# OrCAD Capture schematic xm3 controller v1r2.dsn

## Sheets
1 Revision History: title: Controller; rev: V1.2; company: Wolfspeed; note: 535 W Research Center Blvd.; note: Fayetteville, AR, 72701
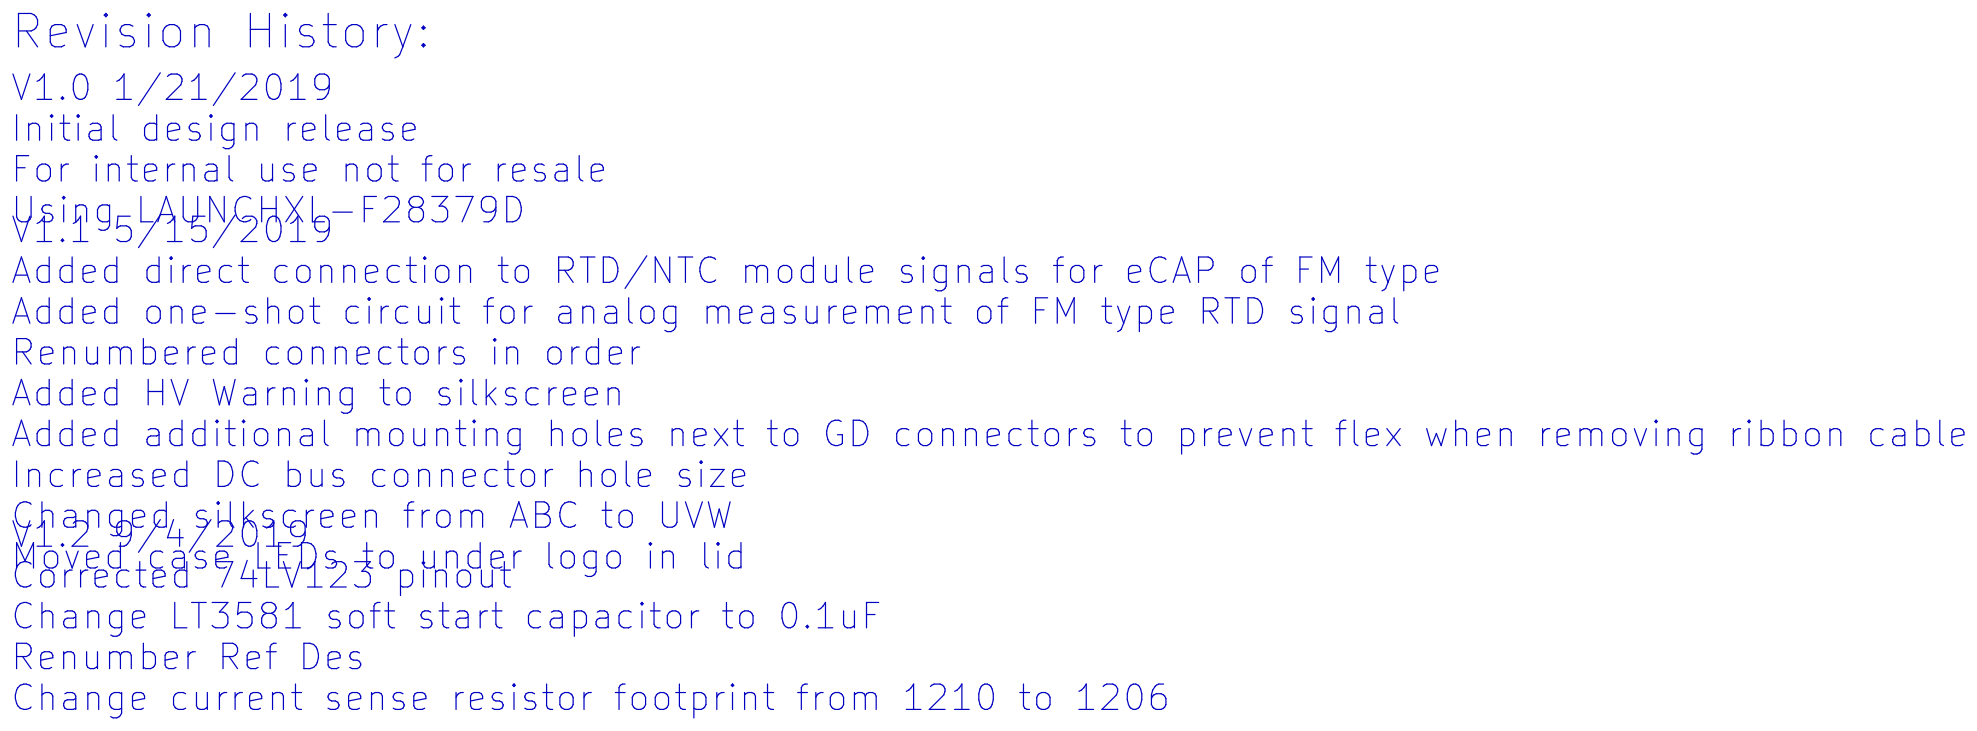
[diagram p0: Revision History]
2 Power Supply: size A
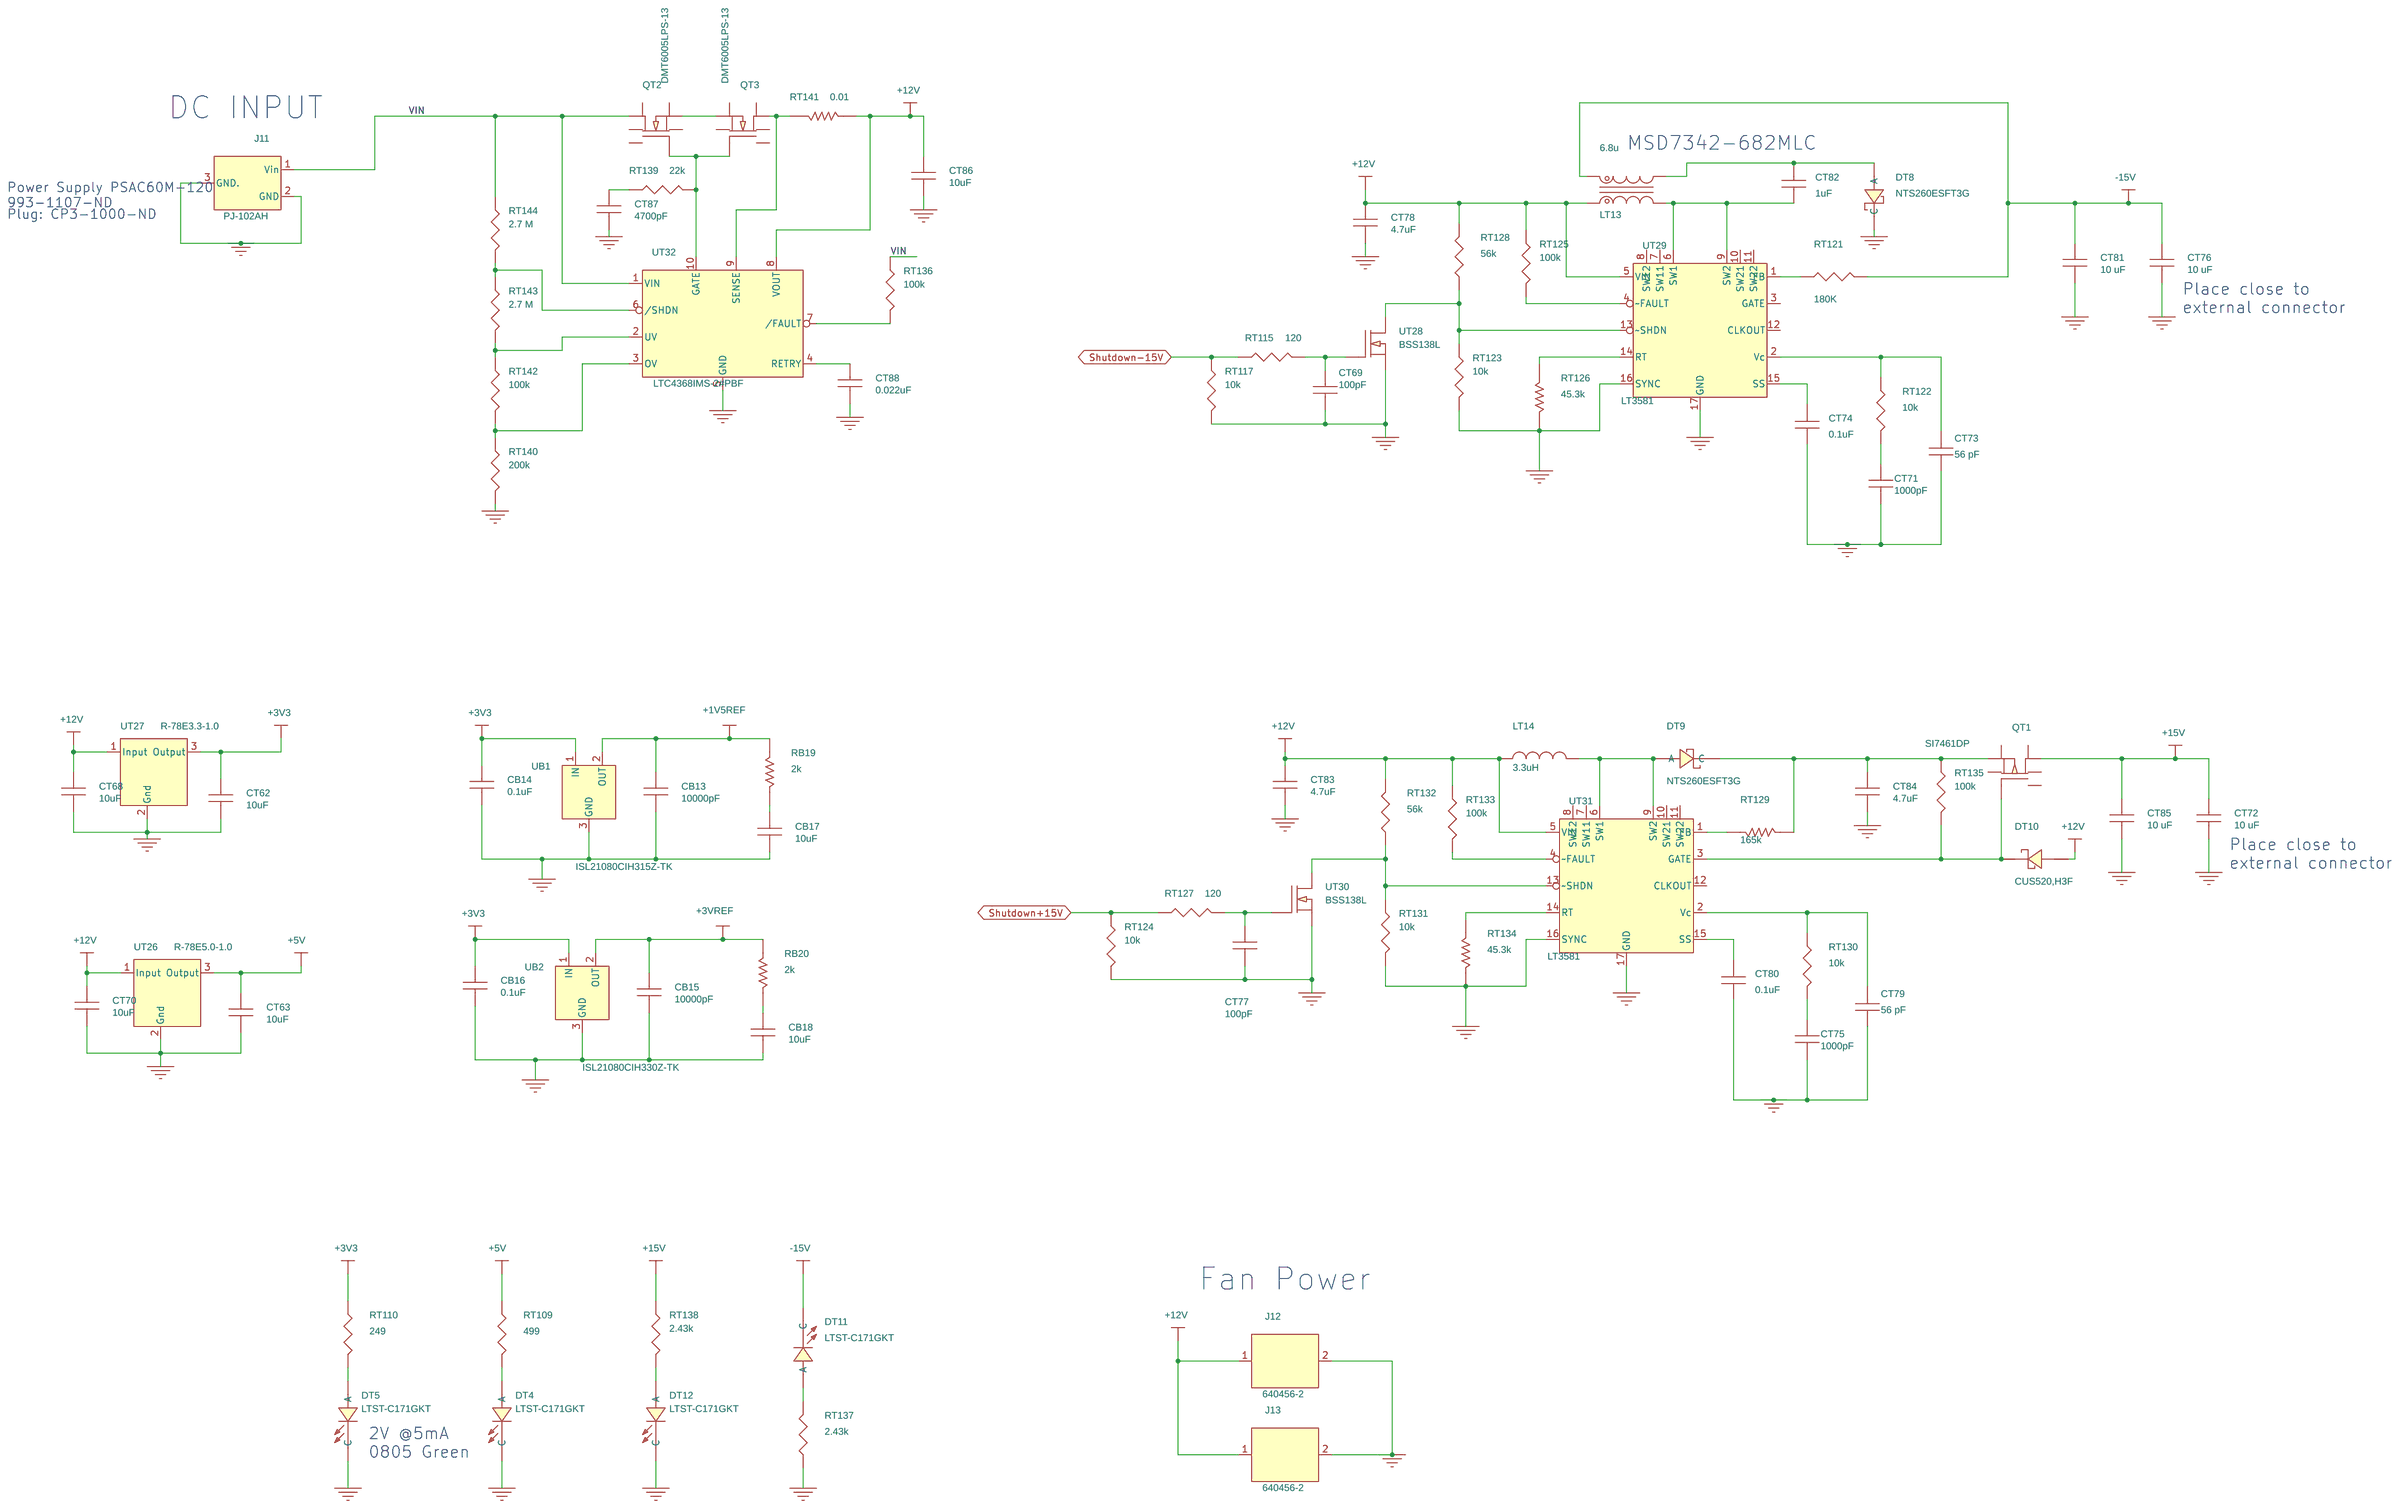
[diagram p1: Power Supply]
3 Voltage Sense: size A
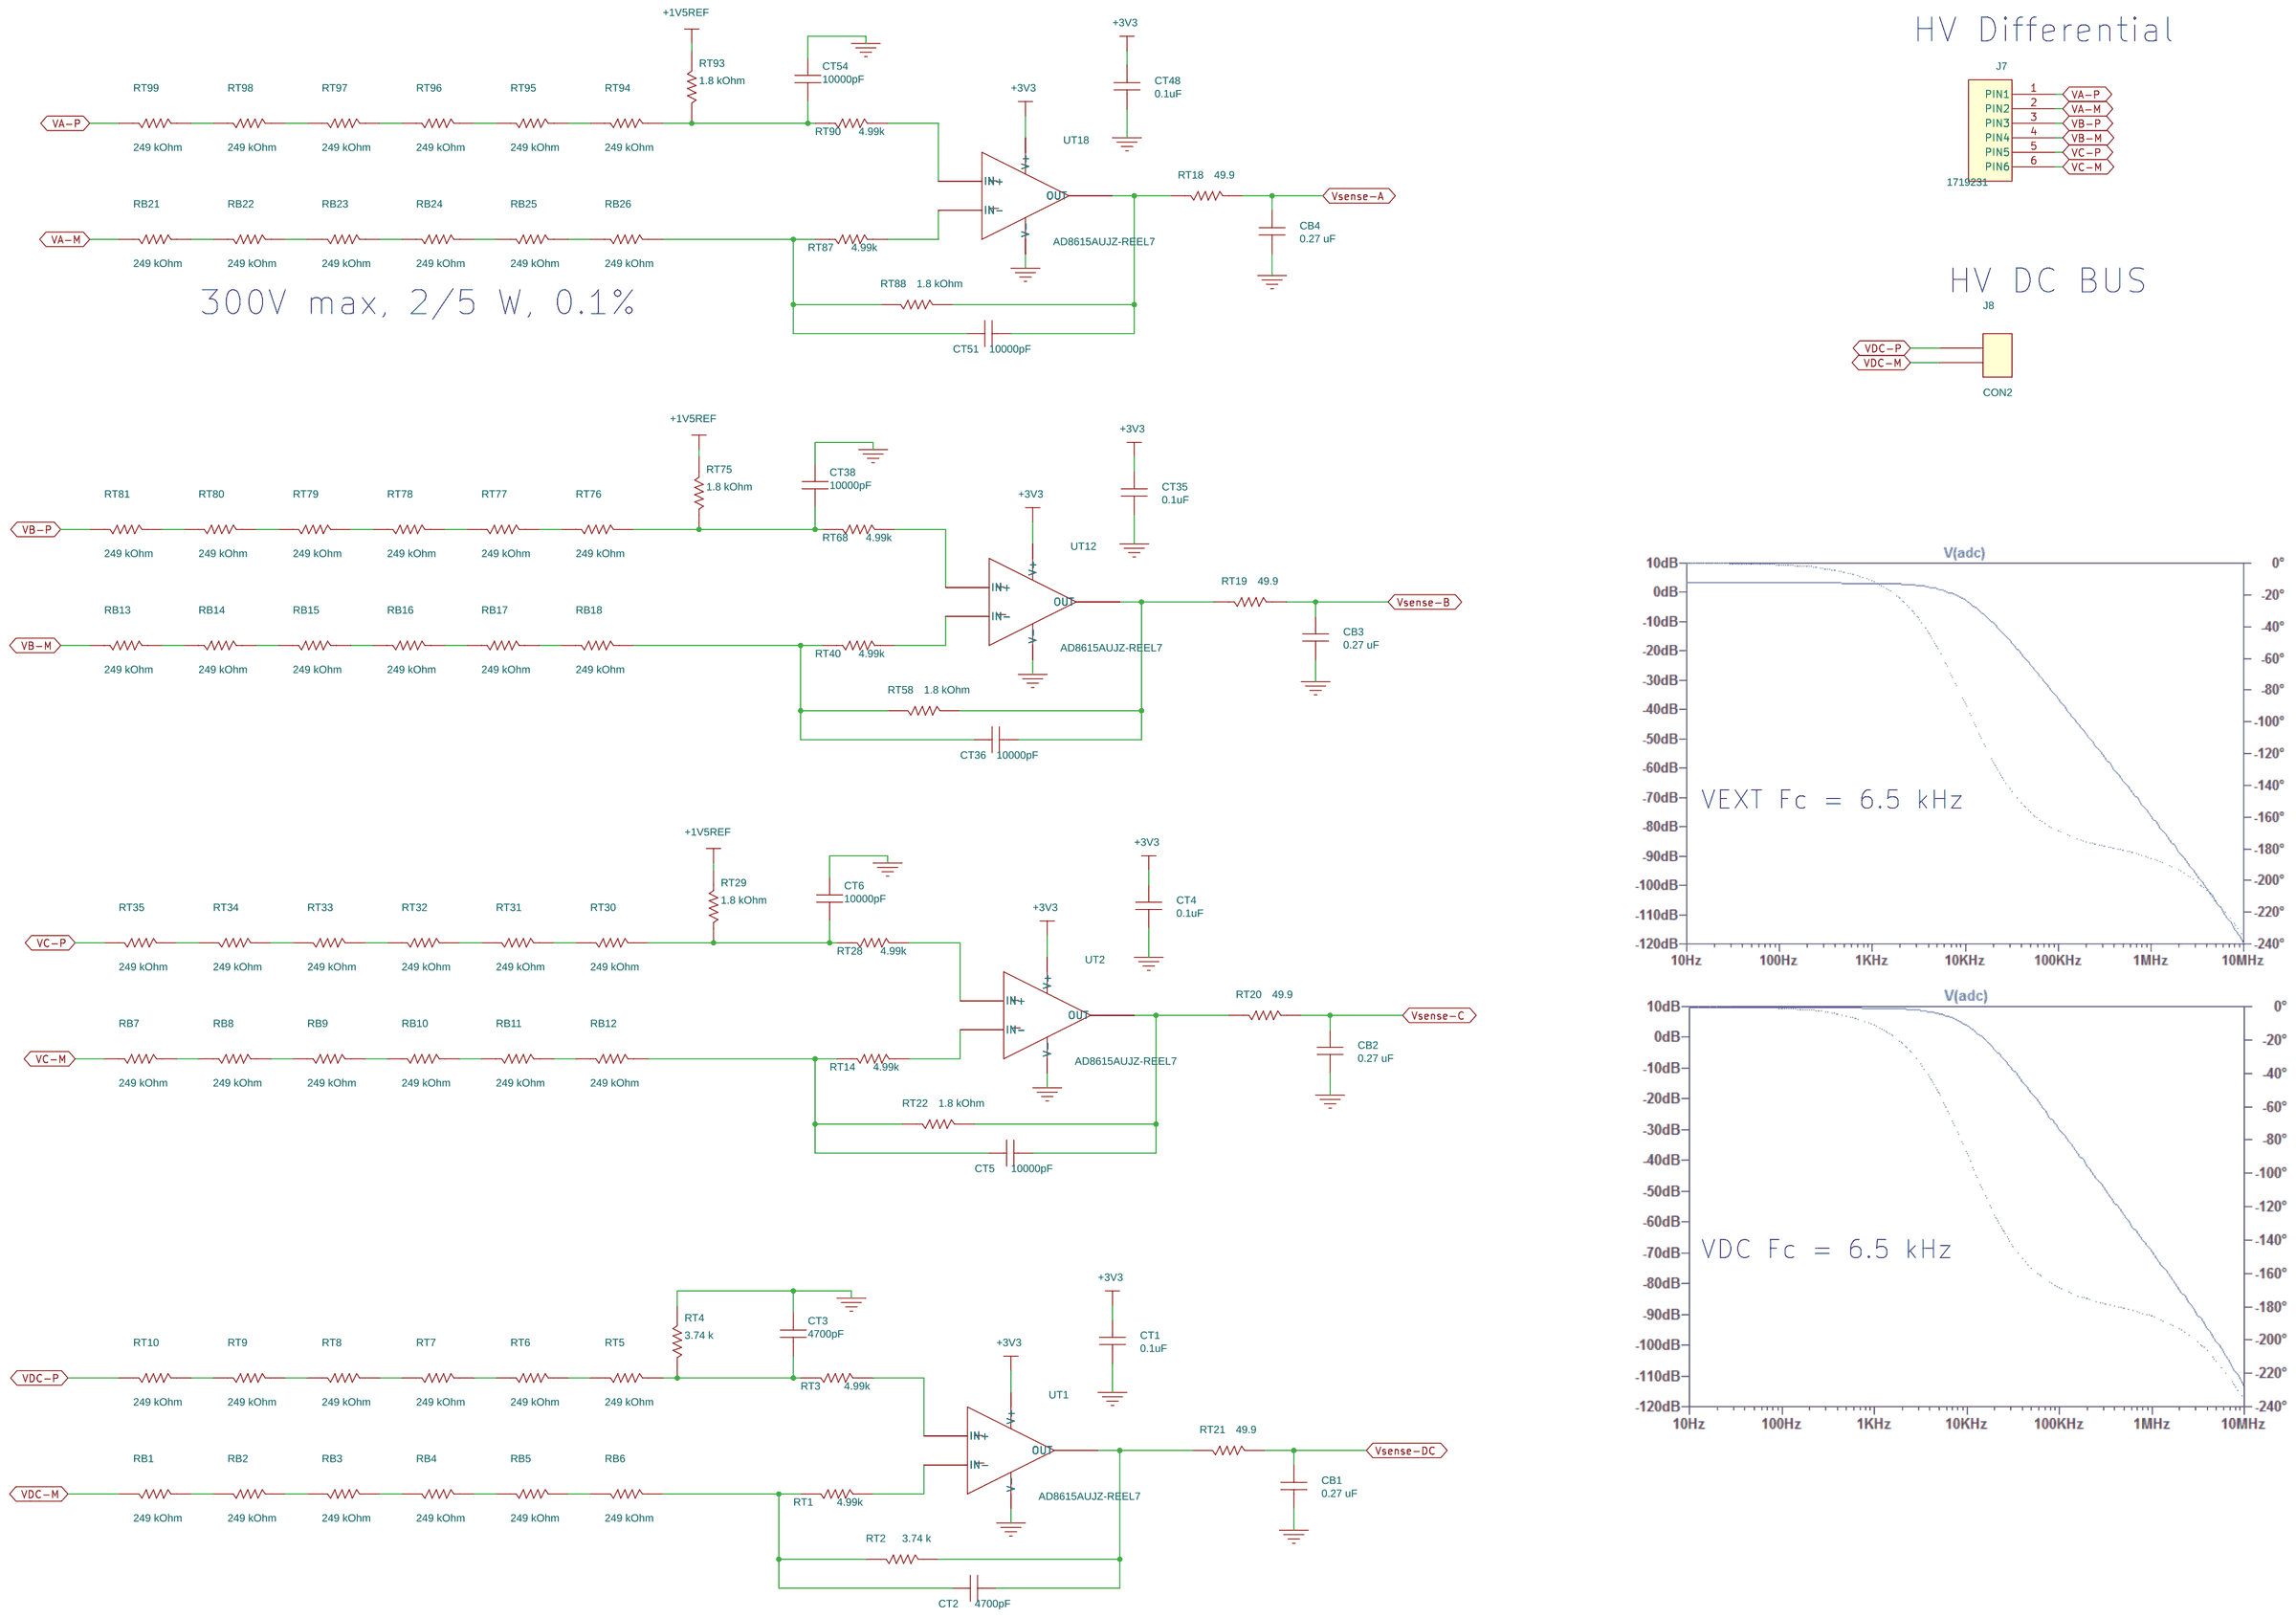
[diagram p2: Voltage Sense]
4 CAN: size A
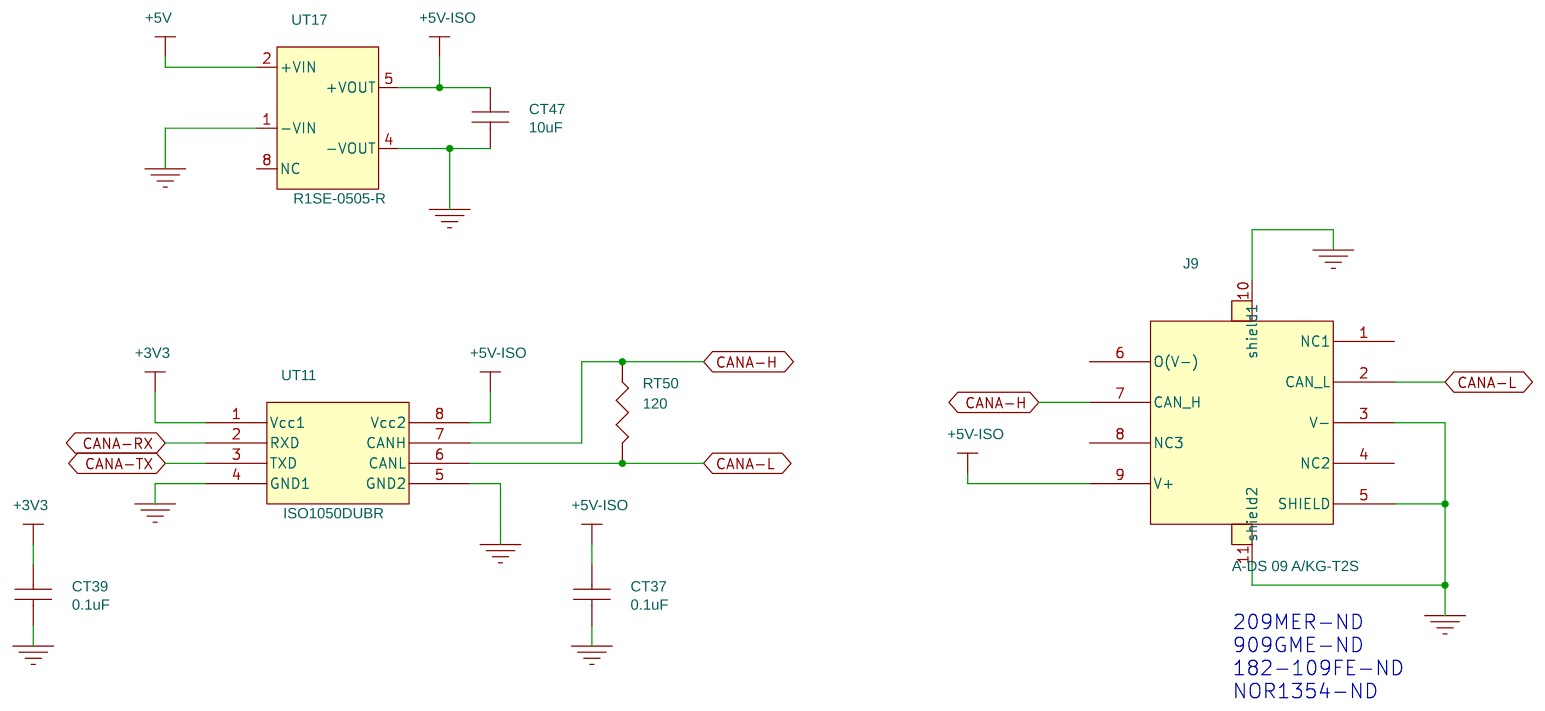
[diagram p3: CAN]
5 Temperature Sense: size A
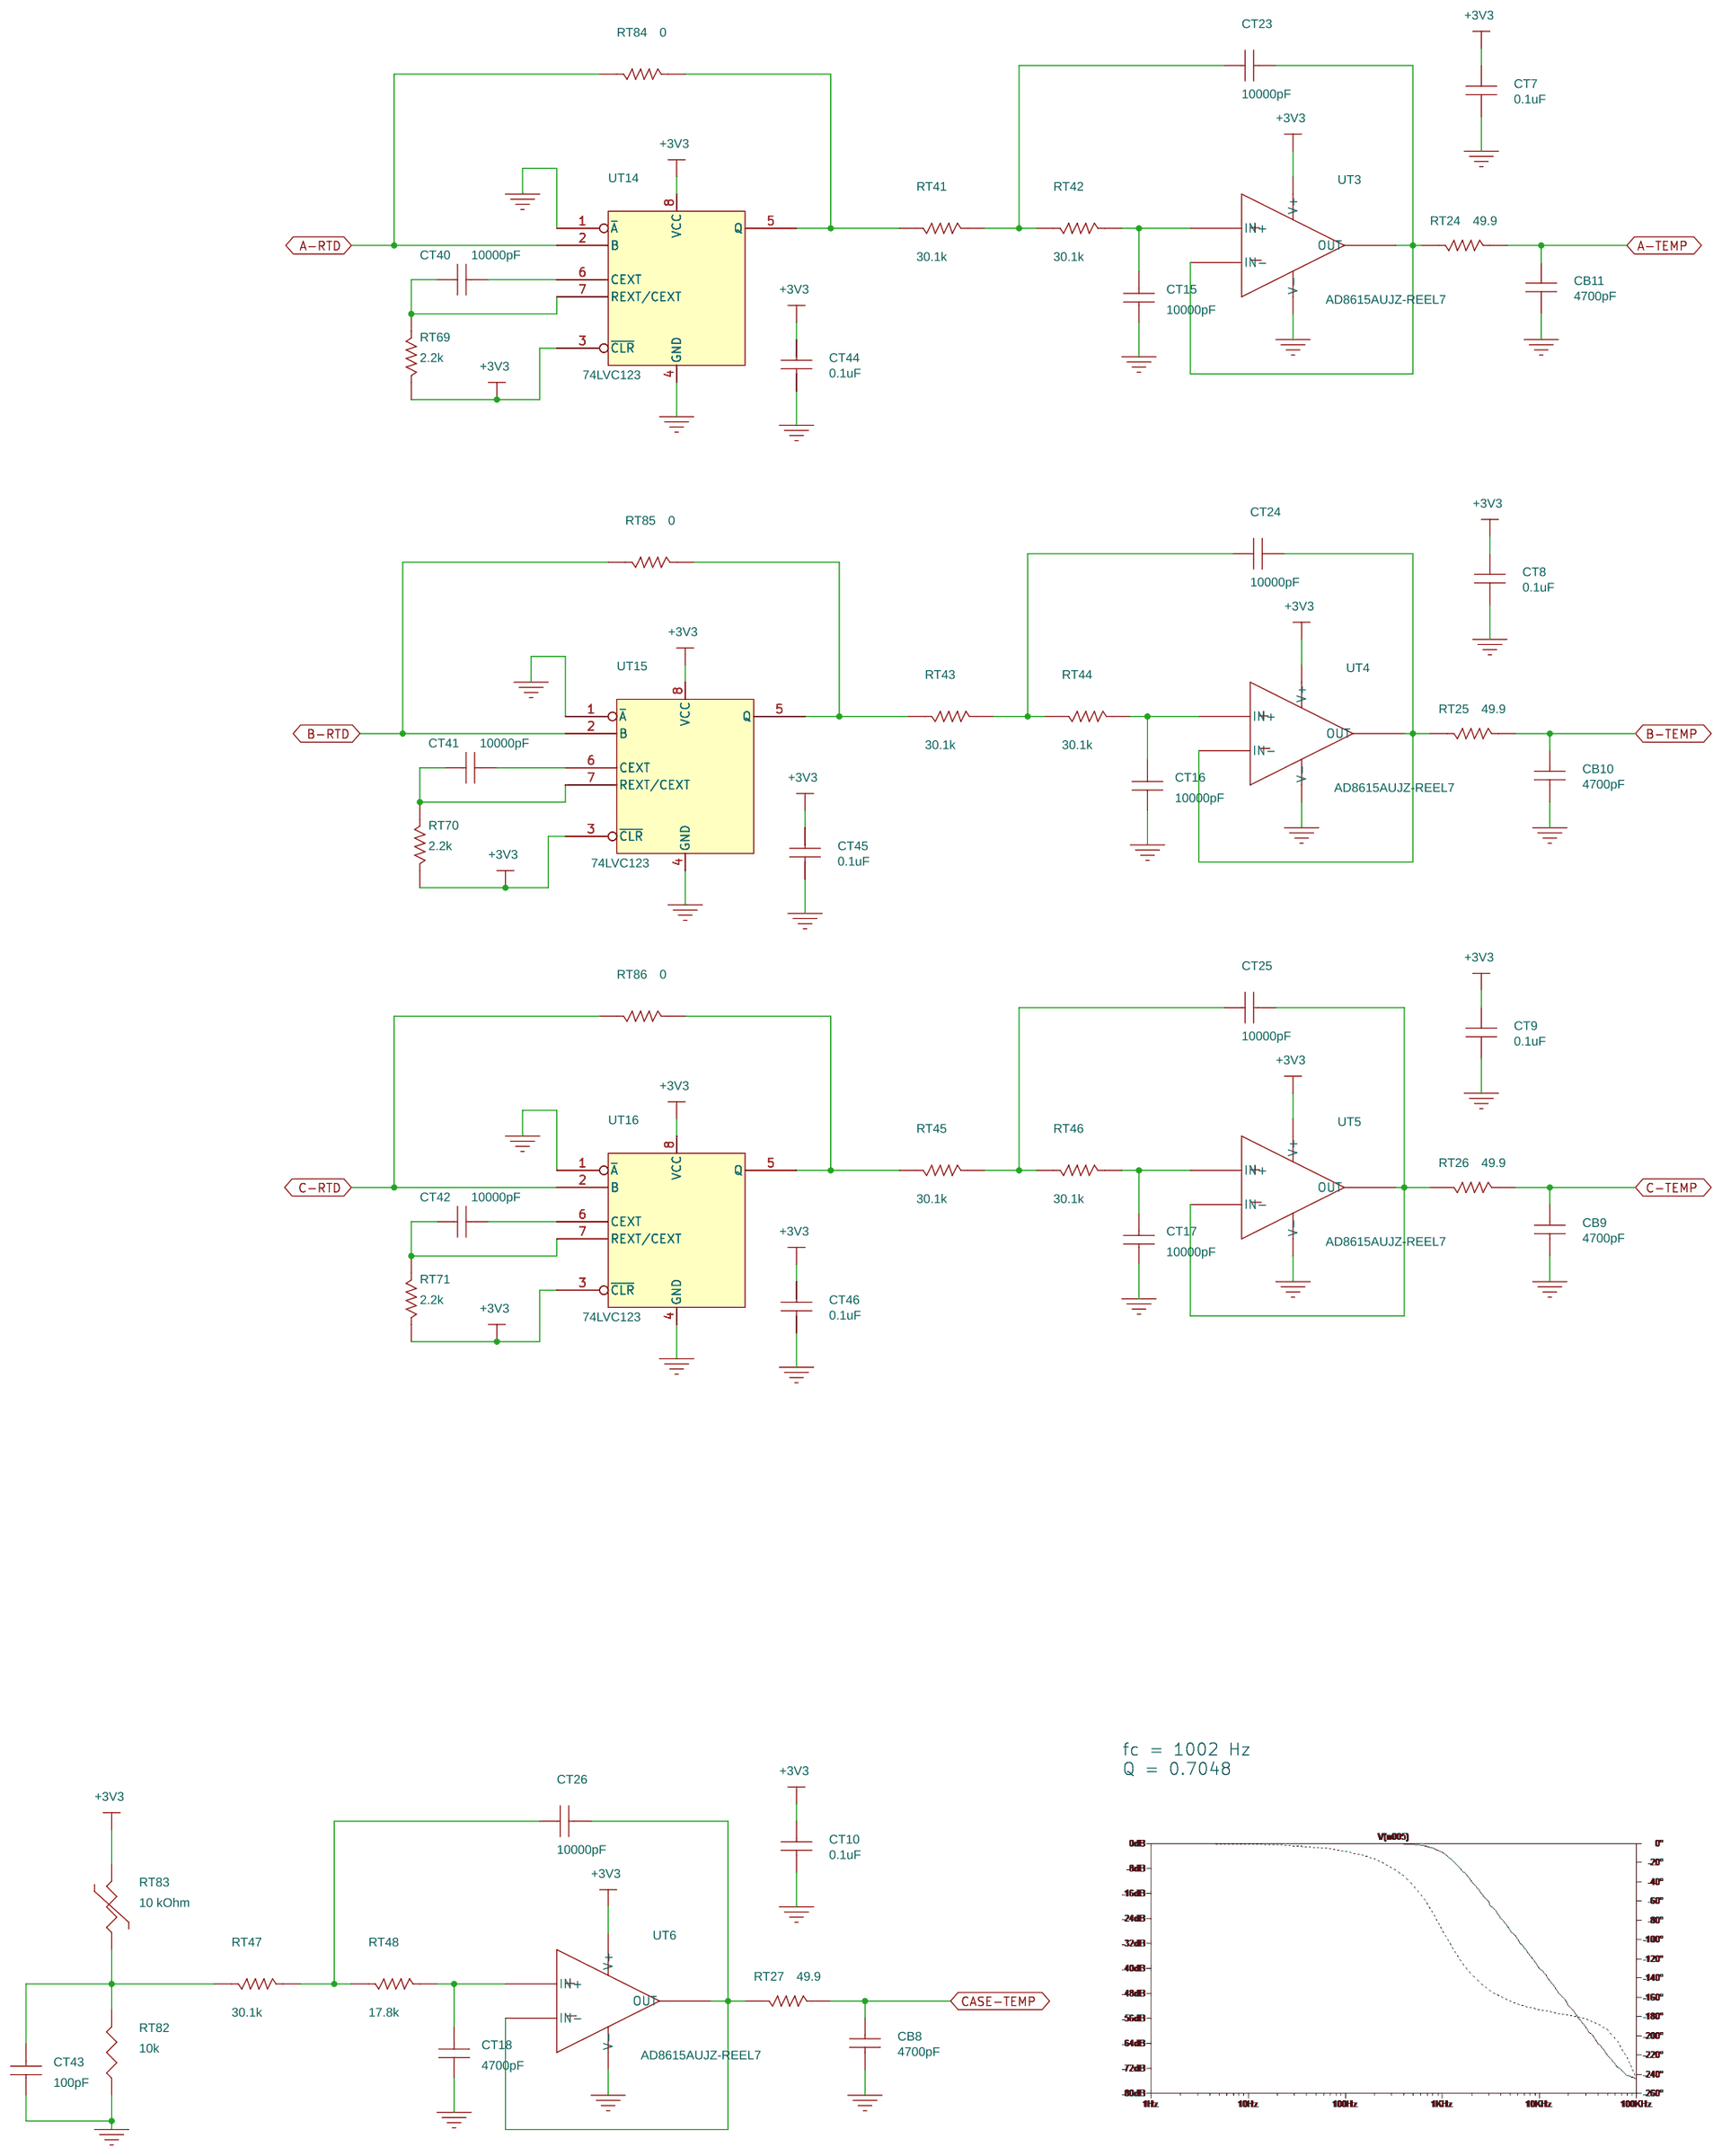
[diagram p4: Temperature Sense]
6 Current Sensors: size A
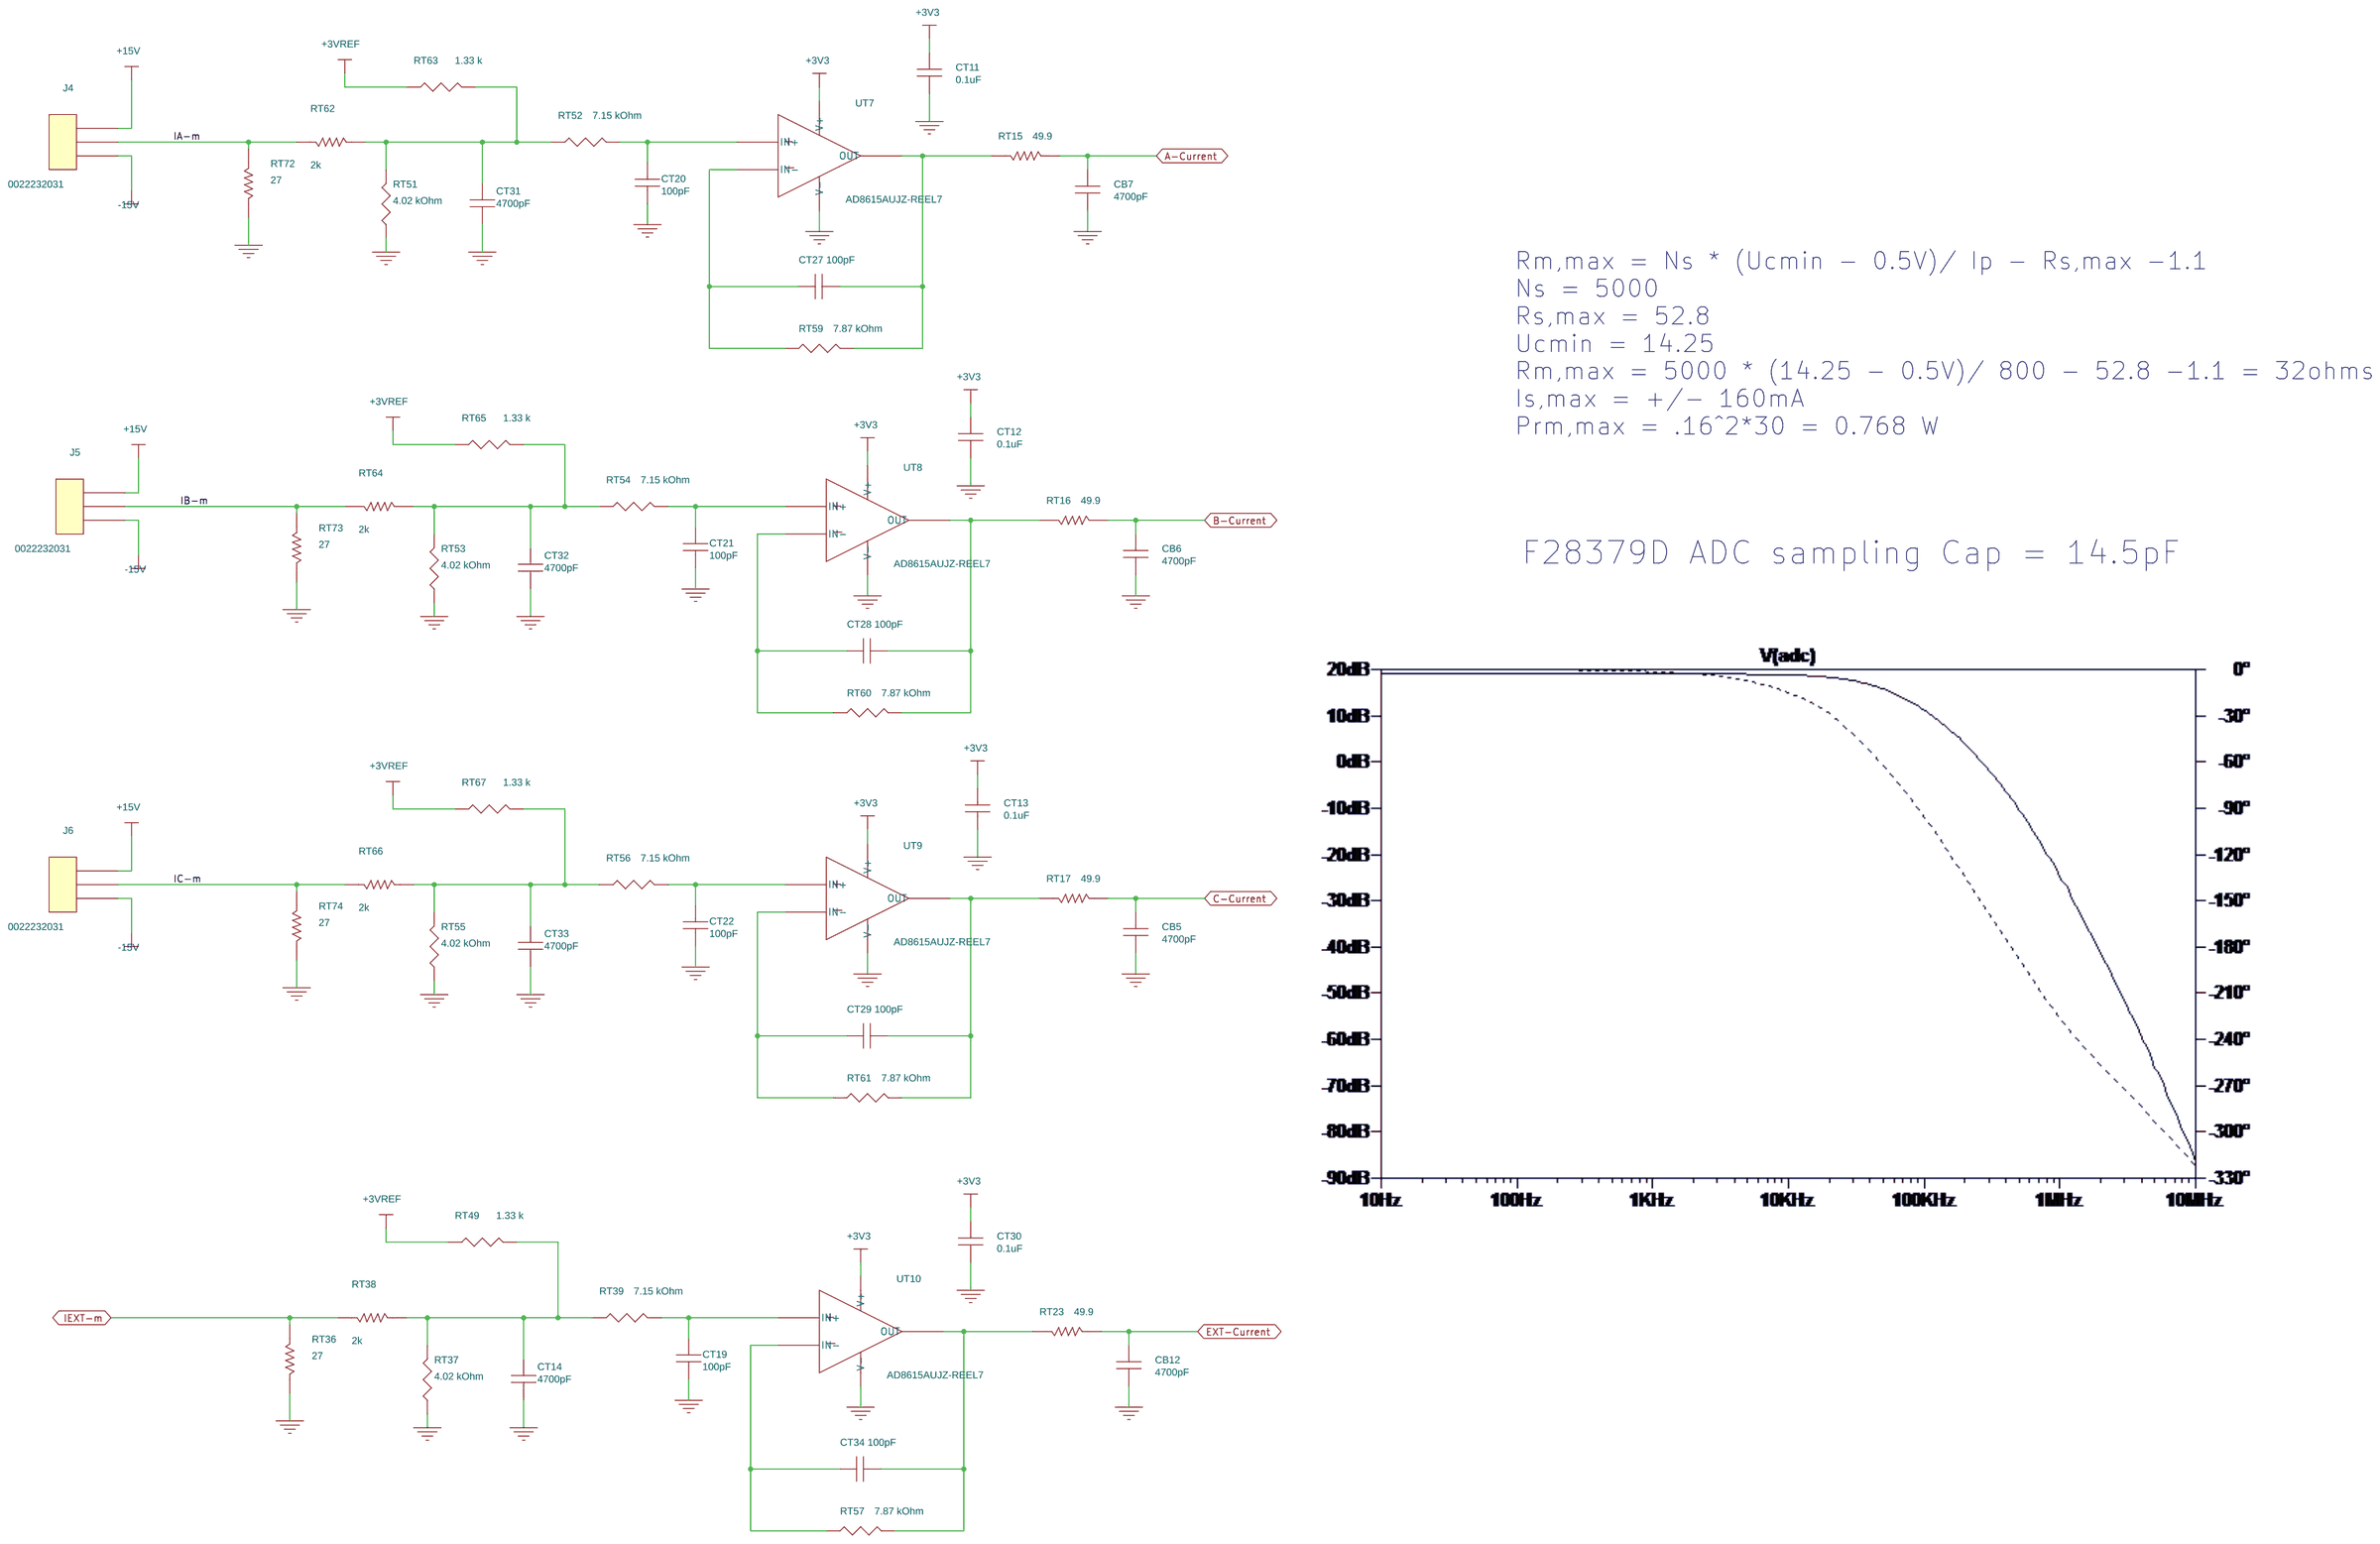
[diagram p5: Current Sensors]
7 LAUNCHPAD: size A
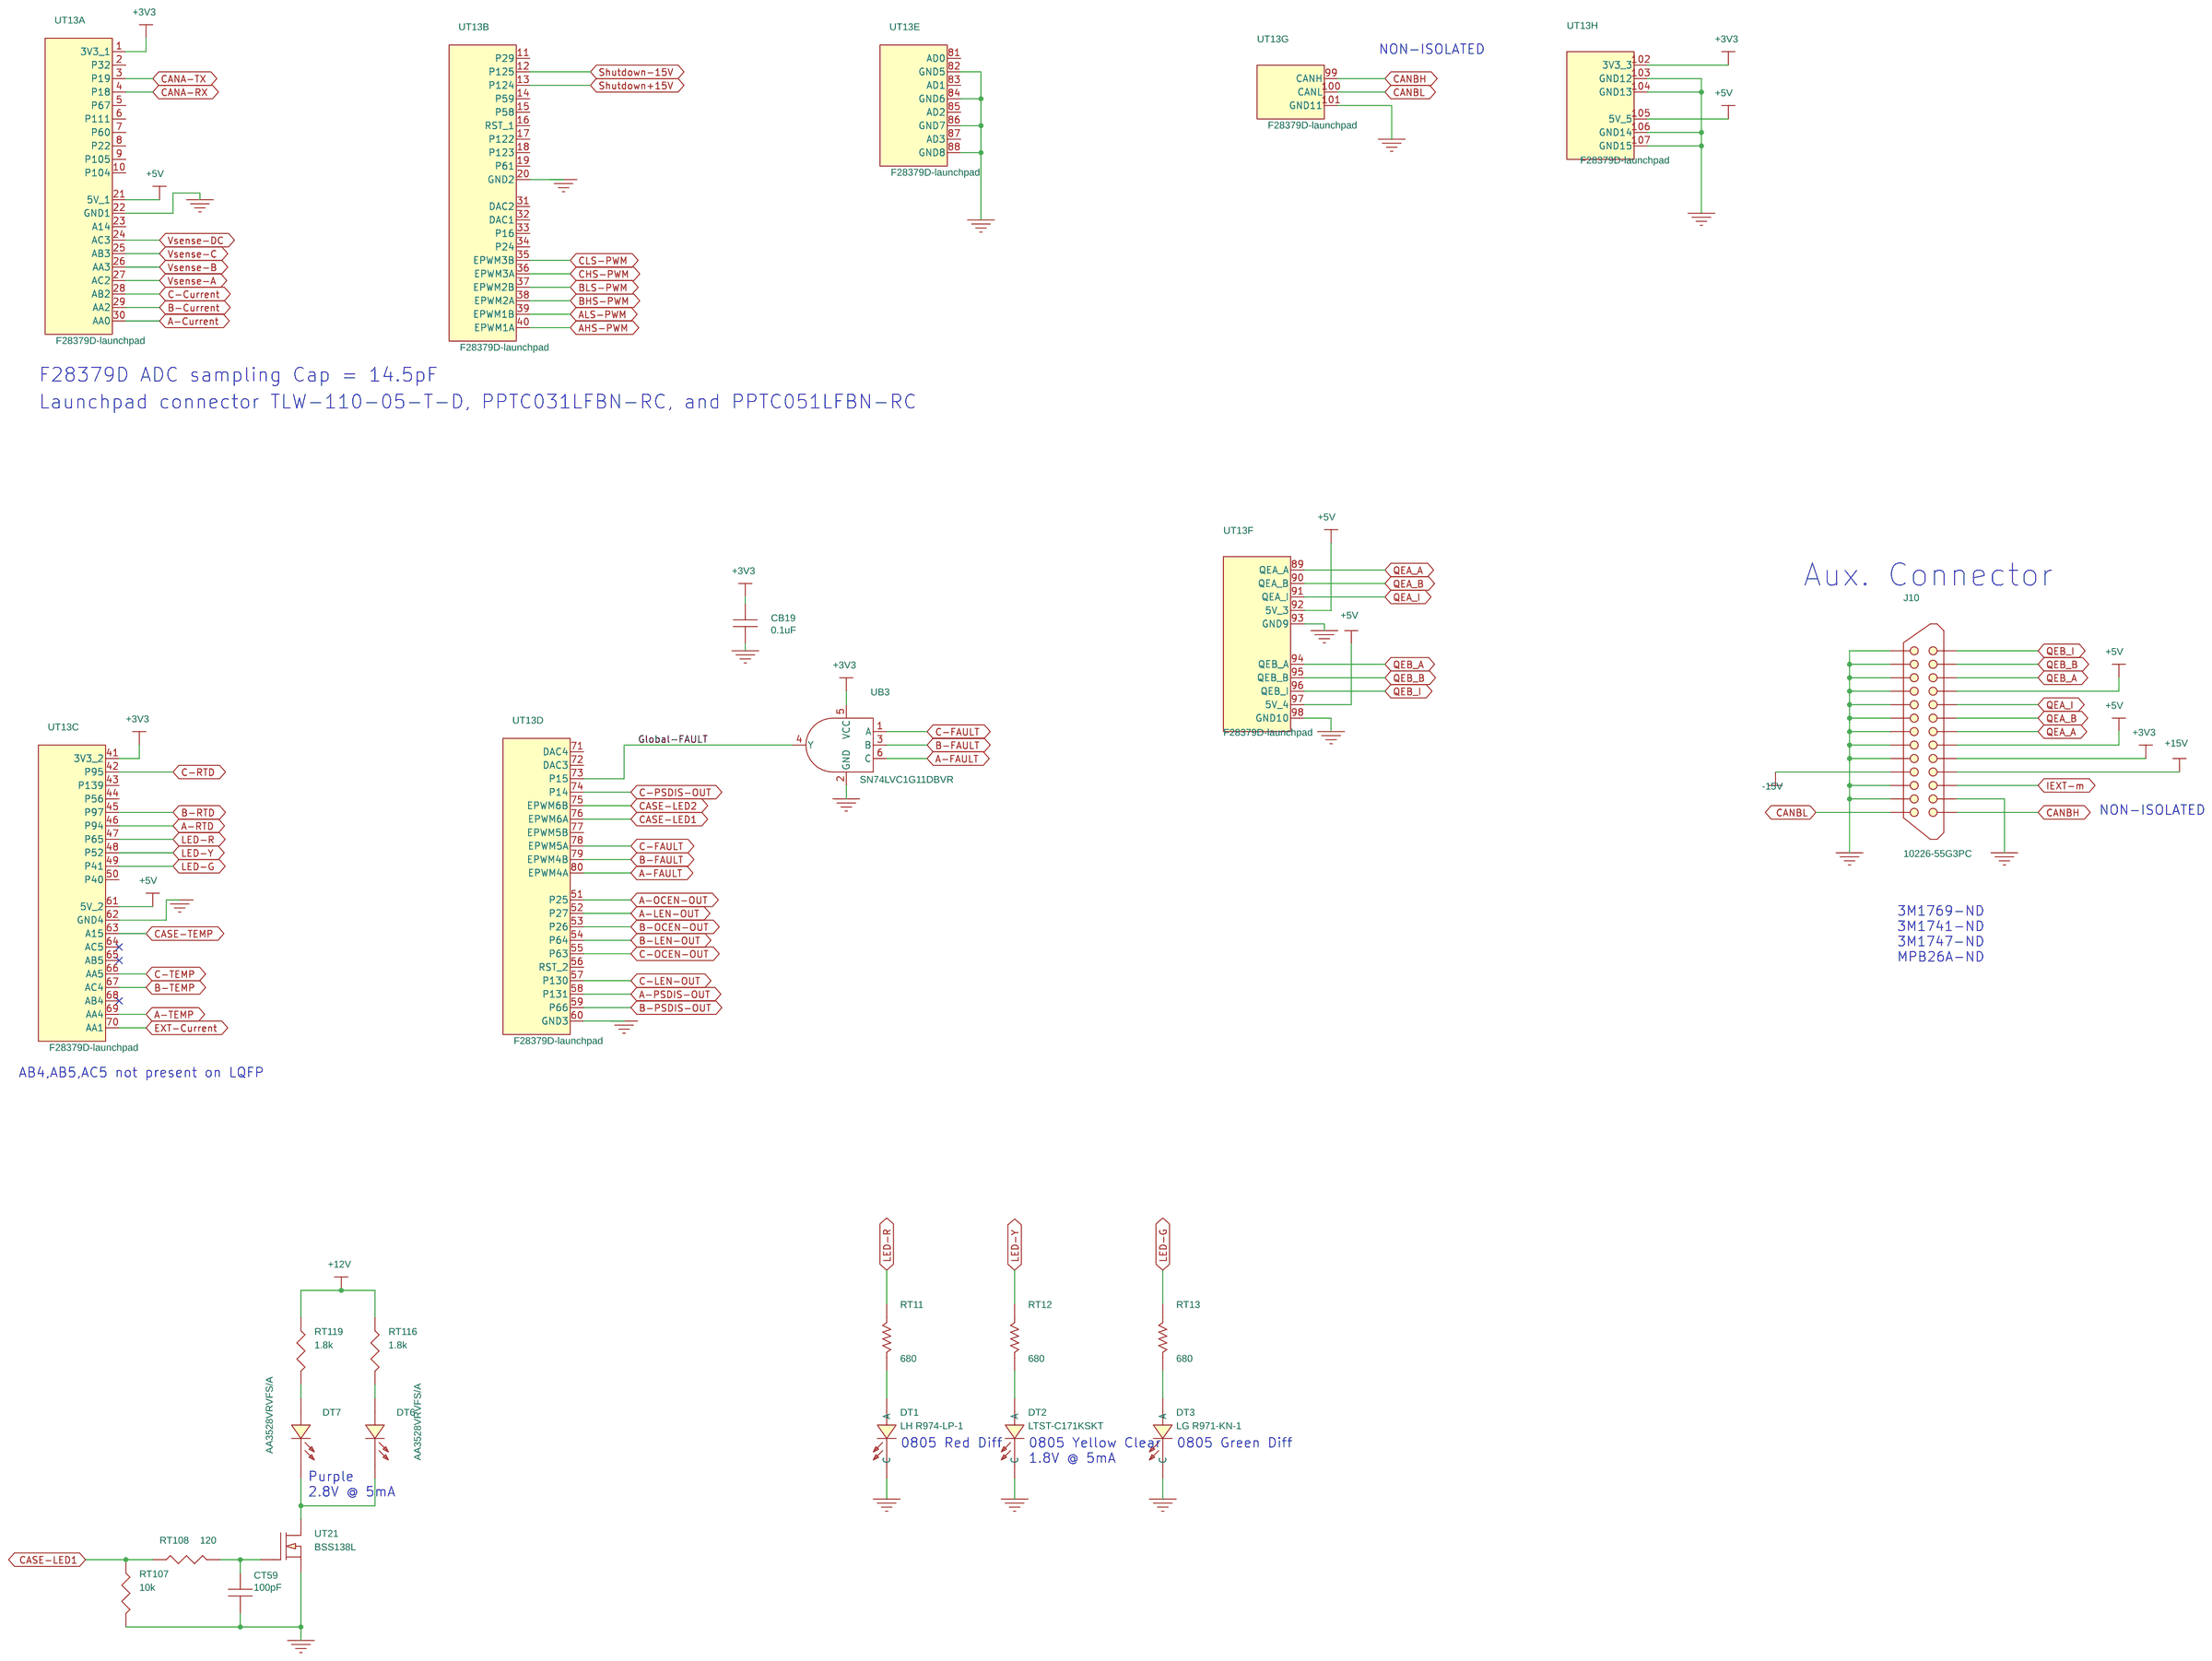
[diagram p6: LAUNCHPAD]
8 Gate Driver Interface: size A
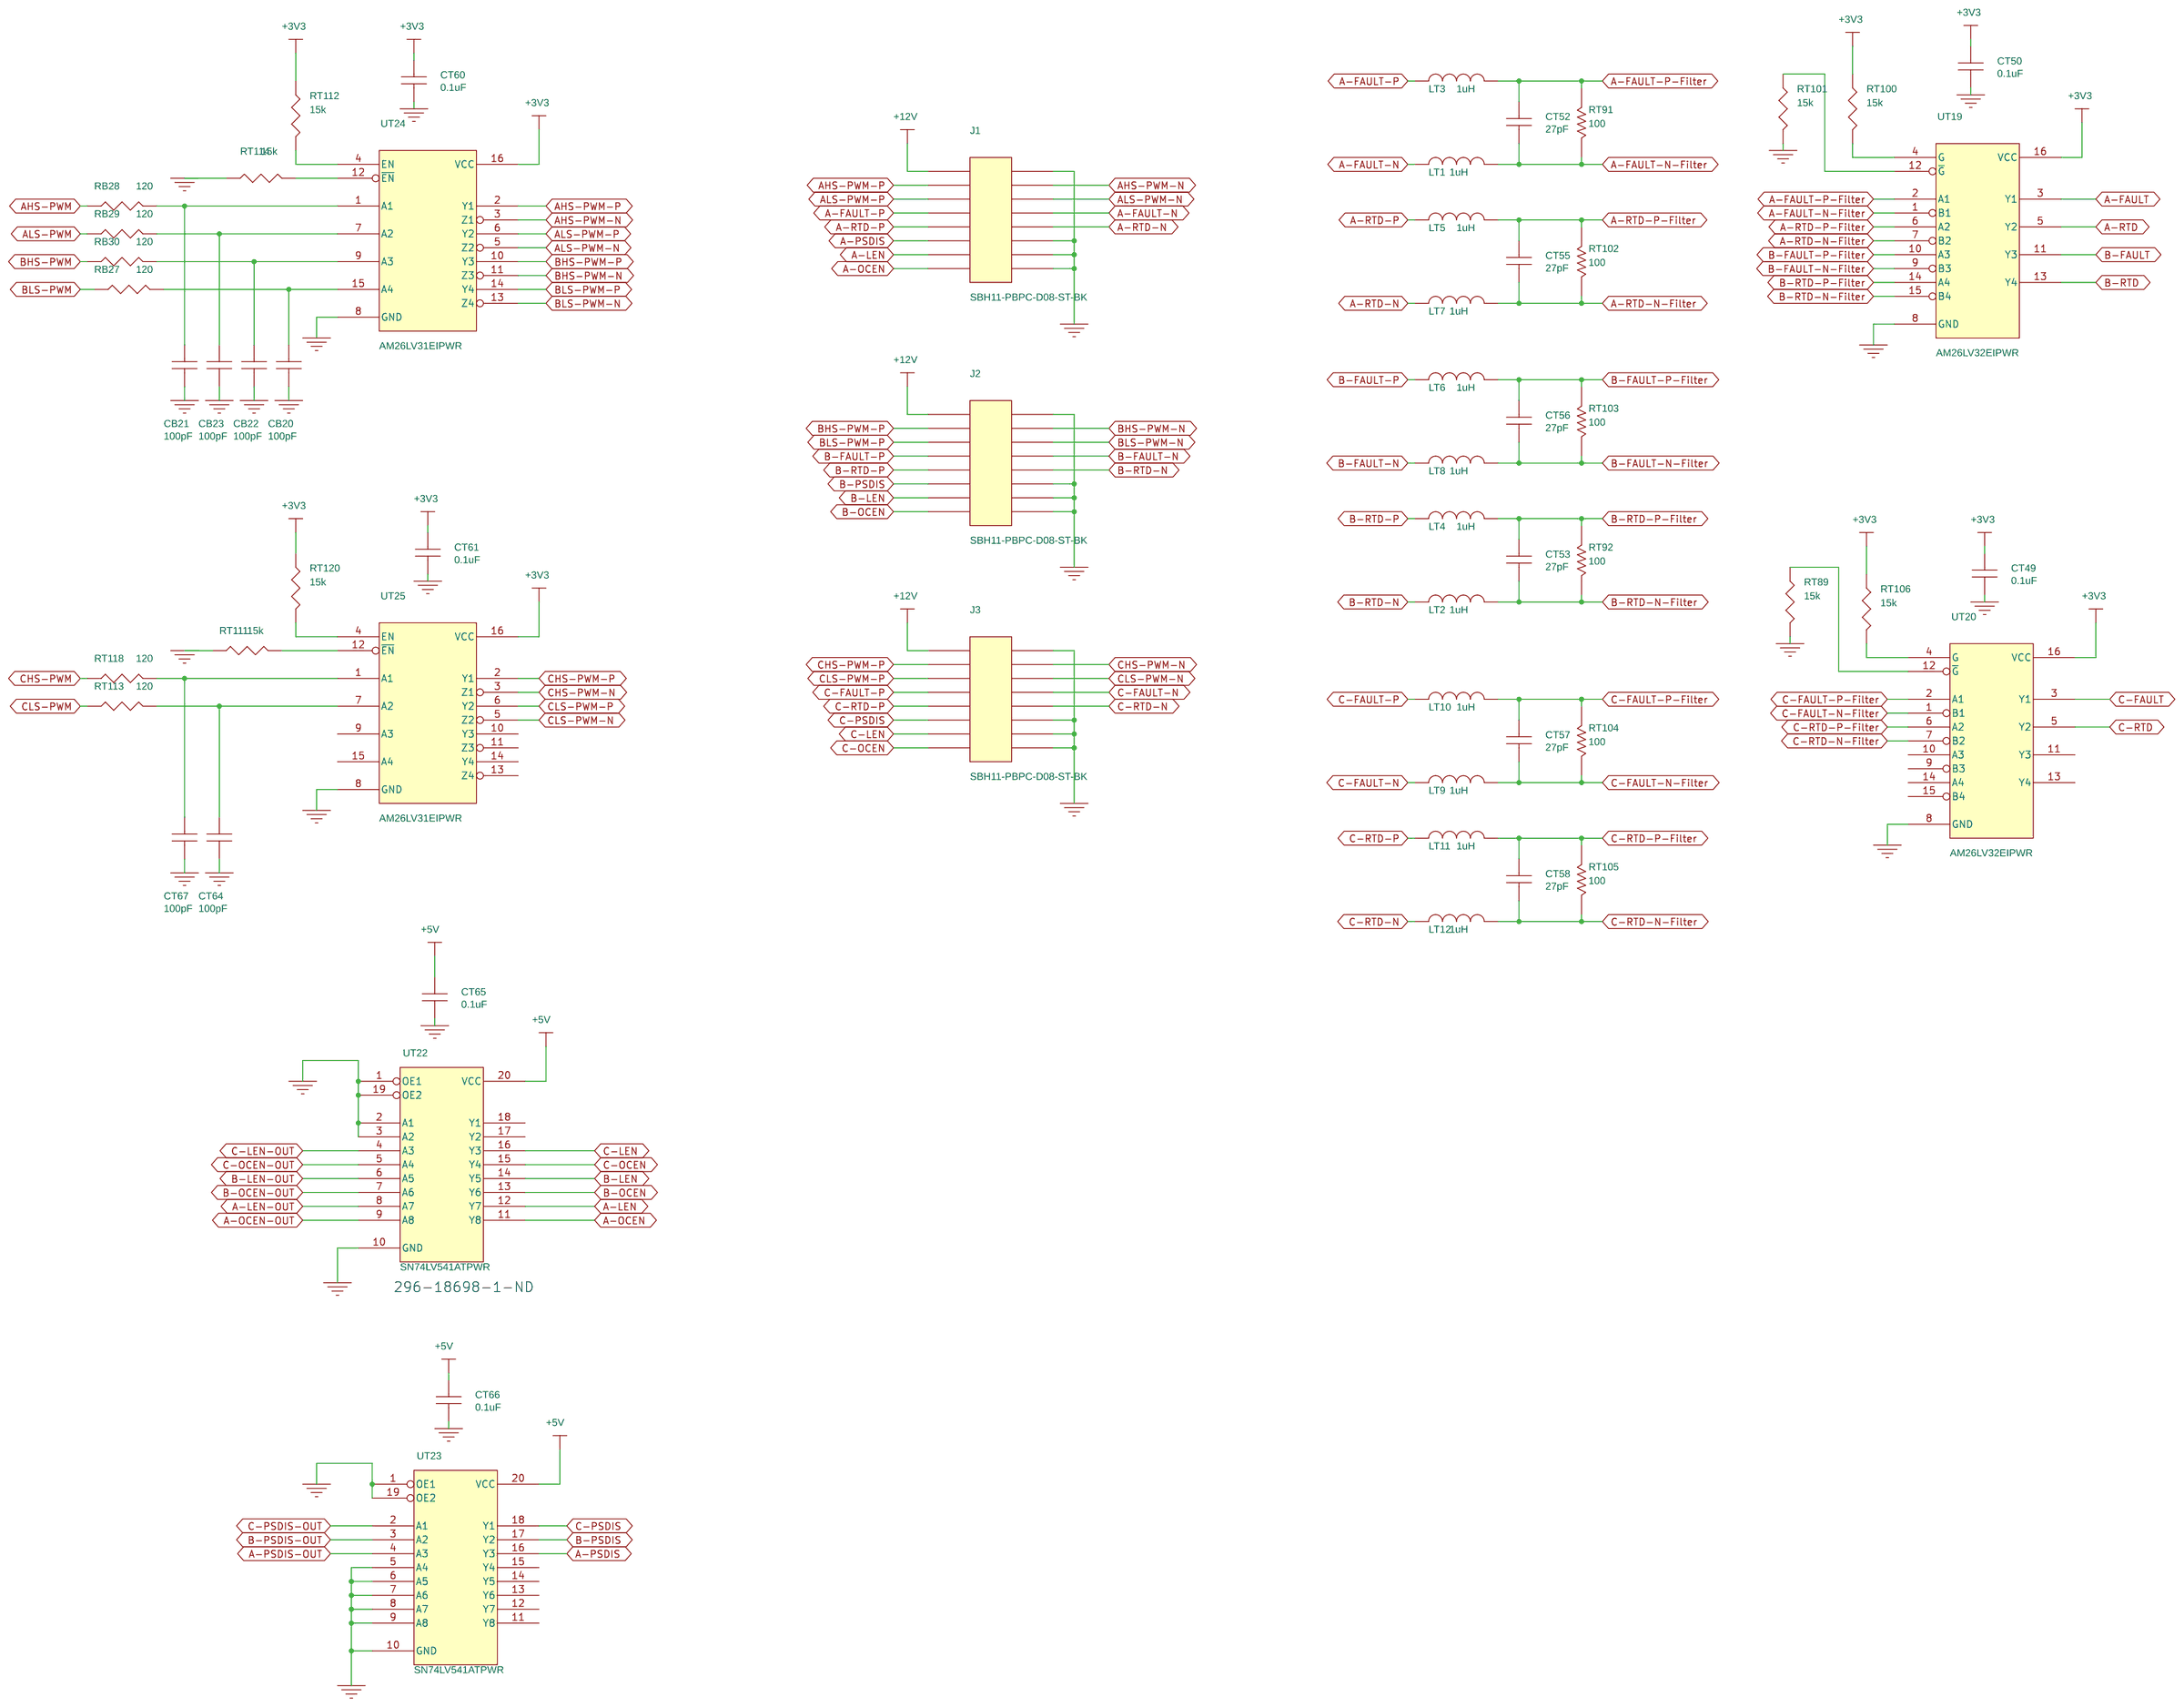
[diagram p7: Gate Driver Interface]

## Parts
sheet CAN
CT37  0.1uF  [CAPC1608X87N]
CT39  0.1uF  [CAPC1608X87N]
CT47  10uF  [CAPC2012X135N]
J9  A-DS 09 A/KG-T2S  [DB9]
RT50  120  [RESC1608X55N]
UT11  ISO1050DUBR  [SMD-8_gull_wing_V2]
UT17  R1SE-0505-R  [8-smd-5leads]
sheet Current Sensors
CB5  4700pF  [c_0603]
CB6  4700pF  [c_0603]
CB7  4700pF  [c_0603]
CB12  4700pF  [c_0603]
CT11  0.1uF  [CAPC1608X87N]
CT12  0.1uF  [CAPC1608X87N]
CT13  0.1uF  [CAPC1608X87N]
CT14  4700pF  [c_0603]
CT19  100pF  [CAPC1608X90N]
CT20  100pF  [CAPC1608X90N]
CT21  100pF  [CAPC1608X90N]
CT22  100pF  [CAPC1608X90N]
CT27  100pF  [CAPC1608X90N]
CT28  100pF  [CAPC1608X90N]
CT29  100pF  [CAPC1608X90N]
CT30  0.1uF  [CAPC1608X87N]
CT31  4700pF  [c_0603]
CT32  4700pF  [c_0603]
CT33  4700pF  [c_0603]
CT34  100pF  [CAPC1608X90N]
J4  0022232031  [CON_1x3_vert_lock]
J5  0022232031  [CON_1x3_vert_lock]
J6  0022232031  [CON_1x3_vert_lock]
RT15  49.9  [RESC1608X55N]
RT16  49.9  [RESC1608X55N]
RT17  49.9  [RESC1608X55N]
RT23  49.9  [RESC1608X55N]
RT36  27  [RESC3216X65N]
RT37  4.02 kOhm  [RESC1608X55N]
RT38  2k  [RESC1608X55N]
RT39  7.15 kOhm  [RESC1608X55N]
RT49  1.33 k  [RESC1608X55N]
RT51  4.02 kOhm  [RESC1608X55N]
RT52  7.15 kOhm  [RESC1608X55N]
RT53  4.02 kOhm  [RESC1608X55N]
RT54  7.15 kOhm  [RESC1608X55N]
RT55  4.02 kOhm  [RESC1608X55N]
RT56  7.15 kOhm  [RESC1608X55N]
RT57  7.87 kOhm  [RESC1608X55N]
RT59  7.87 kOhm  [RESC1608X55N]
RT60  7.87 kOhm  [RESC1608X55N]
RT61  7.87 kOhm  [RESC1608X55N]
RT62  2k  [RESC1608X55N]
RT63  1.33 k  [RESC1608X55N]
RT64  2k  [RESC1608X55N]
RT65  1.33 k  [RESC1608X55N]
RT66  2k  [RESC1608X55N]
RT67  1.33 k  [RESC1608X55N]
RT72  27  [RESC3216X65N]
RT73  27  [RESC3216X65N]
RT74  27  [RESC3216X65N]
UT7  AD8615AUJZ-REEL7  [sot23-5_0_95x2_70p_h1_22]
UT8  AD8615AUJZ-REEL7  [sot23-5_0_95x2_70p_h1_22]
UT9  AD8615AUJZ-REEL7  [sot23-5_0_95x2_70p_h1_22]
UT10  AD8615AUJZ-REEL7  [sot23-5_0_95x2_70p_h1_22]
sheet Gate Driver Interface
CB20  100pF  [CAPC1608X90N]
CB21  100pF  [CAPC1608X90N]
CB22  100pF  [CAPC1608X90N]
CB23  100pF  [CAPC1608X90N]
CT49  0.1uF  [CAPC1608X87N]
CT50  0.1uF  [CAPC1608X87N]
CT52  27pF  [CAPC1608X90N]
CT53  27pF  [CAPC1608X90N]
CT55  27pF  [CAPC1608X90N]
CT56  27pF  [CAPC1608X90N]
CT57  27pF  [CAPC1608X90N]
CT58  27pF  [CAPC1608X90N]
CT60  0.1uF  [CAPC1608X87N]
CT61  0.1uF  [CAPC1608X87N]
CT64  100pF  [CAPC1608X90N]
CT65  0.1uF  [CAPC1608X87N]
CT66  0.1uF  [CAPC1608X87N]
CT67  100pF  [CAPC1608X90N]
J1  SBH11-PBPC-D08-ST-BK  [CON_2x8_shrouded_corrected]
J2  SBH11-PBPC-D08-ST-BK  [CON_2x8_shrouded_corrected]
J3  SBH11-PBPC-D08-ST-BK  [CON_2x8_shrouded_corrected]
LT1  1uH  [l_0805]
LT2  1uH  [l_0805]
LT3  1uH  [l_0805]
LT4  1uH  [l_0805]
LT5  1uH  [l_0805]
LT6  1uH  [l_0805]
LT7  1uH  [l_0805]
LT8  1uH  [l_0805]
LT9  1uH  [l_0805]
LT10  1uH  [l_0805]
LT11  1uH  [l_0805]
LT12  1uH  [l_0805]
RB27  120  [RESC1608X55N]
RB28  120  [RESC1608X55N]
RB29  120  [RESC1608X55N]
RB30  120  [RESC1608X55N]
RT89  15k  [RESC1608X55N]
RT91  100  [RESC1608X55N]
RT92  100  [RESC1608X55N]
RT100  15k  [RESC1608X55N]
RT101  15k  [RESC1608X55N]
RT102  100  [RESC1608X55N]
RT103  100  [RESC1608X55N]
RT104  100  [RESC1608X55N]
RT105  100  [RESC1608X55N]
RT106  15k  [RESC1608X55N]
RT111  15k  [RESC1608X55N]
RT112  15k  [RESC1608X55N]
RT113  120  [RESC1608X55N]
RT114  15k  [RESC1608X55N]
RT118  120  [RESC1608X55N]
RT120  15k  [RESC1608X55N]
UT19  AM26LV32EIPWR  [TSSOP-16P_P65MM]
UT20  AM26LV32EIPWR  [TSSOP-16P_P65MM]
UT22  SN74LV541ATPWR  [SOP65P640X120-20AN]
UT23  SN74LV541ATPWR  [SOP65P640X120-20AN]
UT24  AM26LV31EIPWR  [TSSOP-16P_P65MM]
UT25  AM26LV31EIPWR  [TSSOP-16P_P65MM]
sheet LAUNCHPAD
CB19  0.1uF  [CAPC1608X87N]
CT59  100pF  [CAPC1608X90N]
DT1  LH R974-LP-1  [D_0805]
DT2  LTST-C171KSKT  [D_0805]
DT3  LG R971-KN-1  [D_0805]
DT6  AA3528VRVFS/A  [D_1409]
DT7  AA3528VRVFS/A  [D_1409]
J10  10226-55G3PC  [MDR-26]
RT11  680  [RESC1608X55N]
RT12  680  [RESC1608X55N]
RT13  680  [RESC1608X55N]
RT107  10k  [RESC1608X65N]
RT108  120  [RESC1608X55N]
RT116  1.8k  [RESC2013X65N]
RT119  1.8k  [RESC2013X65N]
UB3  SN74LVC1G11DBVR  [SOT_23_6]
UT13  F28379D-launchpad  [F28379D-Launchpad-1]  (sections A,B,C,D,E,F,G,H)
UT21  BSS138L  [SOT_23_3]
sheet Power Supply
CB13  10000pF  [CAPC1608X90N]
CB14  0.1uF  [CAPC1608X87N]
CB15  10000pF  [CAPC1608X90N]
CB16  0.1uF  [CAPC1608X87N]
CB17  10uF  [CAPC1608X90N]
CB18  10uF  [CAPC1608X90N]
CT62  10uF  [CAPC2012X135N]
CT63  10uF  [CAPC2012X135N]
CT68  10uF  [CAPC2012X135N]
CT69  100pF  [CAPC1608X90N]
CT70  10uF  [CAPC2012X135N]
CT71  1000pF  [CAPC1608X90N]
CT72  10 uF  [CAPC3216X180N]
CT73  56 pF  [CAPC1608X90N]
CT74  0.1uF  [CAPC1608X90N]
CT75  1000pF  [CAPC1608X90N]
CT76  10 uF  [CAPC3216X180N]
CT77  100pF  [CAPC1608X90N]
CT78  4.7uF  [CAPc3216X180N]
CT79  56 pF  [CAPC1608X90N]
CT80  0.1uF  [CAPC1608X90N]
CT81  10 uF  [CAPC3216X180N]
CT82  1uF  [CAPC2012X70N]
CT83  4.7uF  [CAPc3216X180N]
CT84  4.7uF  [CAPc3216X180N]
CT85  10 uF  [CAPC3216X180N]
CT86  10uF  [CAPC2012X135N]
CT87  4700pF  [CAPC1608X90N]
CT88  0.022uF  [CAPC2012X70N]
DT4  LTST-C171GKT  [D_0805]
DT5  LTST-C171GKT  [D_0805]
DT8  NTS260ESFT3G  [SOD-123F-AC]
DT9  NTS260ESFT3G  [SOD-123F-AC]
DT10  CUS520,H3F  [SOD-323-AC]
DT11  LTST-C171GKT  [D_0805]
DT12  LTST-C171GKT  [D_0805]
J11  PJ-102AH  [powerjack-PJ102AH]
J12  640456-2  [CON_1x2_vert_lock]
J13  640456-2  [CON_1x2_vert_lock]
LT13  6.8u  [IND-MSD7342]
LT14  3.3uH  [IND-5040]
QT1  SI7461DP  [POWER-SO8]
QT2  DMT6005LPS-13  [POWER-SO8]
QT3  DMT6005LPS-13  [POWER-SO8]
RB19  2k  [RESC1608X55N]
RB20  2k  [RESC1608X55N]
RT109  499  [RESC2012X60N]
RT110  249  [RESC2012X60N]
RT115  120  [RESC1608X55N]
RT117  10k  [RESC1608X65N]
RT121  180K  [RESC1608X55N]
RT122  10k  [RESC1608X65N]
RT123  10k  [RESC1608X65N]
RT124  10k  [RESC1608X65N]
RT125  100k  [RESC1608X55N]
RT126  45.3k  [RESC1608X55N]
RT127  120  [RESC1608X55N]
RT128  56k  [RESC1608X55N]
RT129  165k  [RESC1608X55N]
RT130  10k  [RESC1608X65N]
RT131  10k  [RESC1608X65N]
RT132  56k  [RESC1608X55N]
RT133  100k  [RESC1608X55N]
RT134  45.3k  [RESC1608X55N]
RT135  100k  [RESC1608X55N]
RT136  100k  [RESC1608X55N]
RT137  2.43k  [RESC2012X60N]
RT138  2.43k  [RESC2012X60N]
RT139  22k  [RESC1608X55N]
RT140  200k  [RESC1608X55N]
RT141  0.01  [RESC6432X70N]
RT142  100k  [RESC1608X55N]
RT143  2.7 M  [RESC1608X55N]
RT144  2.7 M  [RESC1608X55N]
UB1  ISL21080CIH315Z-TK  [SOT_23_3]
UB2  ISL21080CIH330Z-TK  [SOT_23_3]
UT26  R-78E5.0-1.0  [TO-220V]
UT27  R-78E3.3-1.0  [TO-220V]
UT28  BSS138L  [SOT_23_3]
UT29  LT3581  [MSOP-16-EP]
UT30  BSS138L  [SOT_23_3]
UT31  LT3581  [MSOP-16-EP]
UT32  LTC4368IMS-2#PBF  [MSOP_10]
sheet Temperature Sense
CB8  4700pF  [c_0603]
CB9  4700pF  [c_0603]
CB10  4700pF  [c_0603]
CB11  4700pF  [c_0603]
CT7  0.1uF  [CAPC1608X87N]
CT8  0.1uF  [CAPC1608X87N]
CT9  0.1uF  [CAPC1608X87N]
CT10  0.1uF  [CAPC1608X87N]
CT15  10000pF  [CAPC1608X90N]
CT16  10000pF  [CAPC1608X90N]
CT17  10000pF  [CAPC1608X90N]
CT18  4700pF  [CAPC1608X90N]
CT23  10000pF  [CAPC1608X90N]
CT24  10000pF  [CAPC1608X90N]
CT25  10000pF  [CAPC1608X90N]
CT26  10000pF  [CAPC1608X90N]
CT40  10000pF  [CAPC1608X90N]
CT41  10000pF  [CAPC1608X90N]
CT42  10000pF  [CAPC1608X90N]
CT43  100pF  [CAPC1608X90N]
CT44  0.1uF  [CAPC1608X87N]
CT45  0.1uF  [CAPC1608X87N]
CT46  0.1uF  [CAPC1608X87N]
RT24  49.9  [RESC1608X55N]
RT25  49.9  [RESC1608X55N]
RT26  49.9  [RESC1608X55N]
RT27  49.9  [RESC1608X55N]
RT41  30.1k  [RESC1608X55N]
RT42  30.1k  [RESC1608X55N]
RT43  30.1k  [RESC1608X55N]
RT44  30.1k  [RESC1608X55N]
RT45  30.1k  [RESC1608X55N]
RT46  30.1k  [RESC1608X55N]
RT47  30.1k  [RESC1608X55N]
RT48  17.8k  [RESC1608X55N]
RT69  2.2k  [RESC1608X55N]
RT70  2.2k  [RESC1608X55N]
RT71  2.2k  [RESC1608X55N]
RT82  10k  [RESC1608X65N]
RT83  10 kOhm  [RESC2012X60N]
RT84  0  [RESC2012X70N]
RT85  0  [RESC2012X70N]
RT86  0  [RESC2012X70N]
UT3  AD8615AUJZ-REEL7  [sot23-5_0_95x2_70p_h1_22]
UT4  AD8615AUJZ-REEL7  [sot23-5_0_95x2_70p_h1_22]
UT5  AD8615AUJZ-REEL7  [sot23-5_0_95x2_70p_h1_22]
UT6  AD8615AUJZ-REEL7  [sot23-5_0_95x2_70p_h1_22]
UT14  74LVC123  [VFSOP-8]
UT15  74LVC123  [VFSOP-8]
UT16  74LVC123  [VFSOP-8]
sheet Voltage Sense
CB1  0.27 uF  [CAPC1608X90N]
CB2  0.27 uF  [CAPC1608X90N]
CB3  0.27 uF  [CAPC1608X90N]
CB4  0.27 uF  [CAPC1608X90N]
CT1  0.1uF  [CAPC1608X87N]
CT2  4700pF  [CAPC1608X90N]
CT3  4700pF  [CAPC1608X90N]
CT4  0.1uF  [CAPC1608X87N]
CT5  10000pF  [CAPC1608X90N]
CT6  10000pF  [CAPC1608X90N]
CT35  0.1uF  [CAPC1608X87N]
CT36  10000pF  [CAPC1608X90N]
CT38  10000pF  [CAPC1608X90N]
CT48  0.1uF  [CAPC1608X87N]
CT51  10000pF  [CAPC1608X90N]
CT54  10000pF  [CAPC1608X90N]
J7  1719231  [Phoenix_SPT5_6PIN]
J8  CON2  [2POS_400mil_Terminal]
RB1  249 kOhm  [RESC3216X65N]
RB2  249 kOhm  [RESC3216X65N]
RB3  249 kOhm  [RESC3216X65N]
RB4  249 kOhm  [RESC3216X65N]
RB5  249 kOhm  [RESC3216X65N]
RB6  249 kOhm  [RESC3216X65N]
RB7  249 kOhm  [RESC3216X65N]
RB8  249 kOhm  [RESC3216X65N]
RB9  249 kOhm  [RESC3216X65N]
RB10  249 kOhm  [RESC3216X65N]
RB11  249 kOhm  [RESC3216X65N]
RB12  249 kOhm  [RESC3216X65N]
RB13  249 kOhm  [RESC3216X65N]
RB14  249 kOhm  [RESC3216X65N]
RB15  249 kOhm  [RESC3216X65N]
RB16  249 kOhm  [RESC3216X65N]
RB17  249 kOhm  [RESC3216X65N]
RB18  249 kOhm  [RESC3216X65N]
RB21  249 kOhm  [RESC3216X65N]
RB22  249 kOhm  [RESC3216X65N]
RB23  249 kOhm  [RESC3216X65N]
RB24  249 kOhm  [RESC3216X65N]
RB25  249 kOhm  [RESC3216X65N]
RB26  249 kOhm  [RESC3216X65N]
RT1  4.99k  [RESC1608X55N]
RT2  3.74 k  [RESC1608X55N]
RT3  4.99k  [RESC1608X55N]
RT4  3.74 k  [RESC1608X55N]
RT5  249 kOhm  [RESC3216X65N]
RT6  249 kOhm  [RESC3216X65N]
RT7  249 kOhm  [RESC3216X65N]
RT8  249 kOhm  [RESC3216X65N]
RT9  249 kOhm  [RESC3216X65N]
RT10  249 kOhm  [RESC3216X65N]
RT14  4.99k  [RESC1608X55N]
RT18  49.9  [RESC1608X55N]
RT19  49.9  [RESC1608X55N]
RT20  49.9  [RESC1608X55N]
RT21  49.9  [RESC1608X55N]
RT22  1.8 kOhm  [RESC1608X55N]
RT28  4.99k  [RESC1608X55N]
RT29  1.8 kOhm  [RESC1608X55N]
RT30  249 kOhm  [RESC3216X65N]
RT31  249 kOhm  [RESC3216X65N]
RT32  249 kOhm  [RESC3216X65N]
RT33  249 kOhm  [RESC3216X65N]
RT34  249 kOhm  [RESC3216X65N]
RT35  249 kOhm  [RESC3216X65N]
RT40  4.99k  [RESC1608X55N]
RT58  1.8 kOhm  [RESC1608X55N]
RT68  4.99k  [RESC1608X55N]
RT75  1.8 kOhm  [RESC1608X55N]
RT76  249 kOhm  [RESC3216X65N]
RT77  249 kOhm  [RESC3216X65N]
RT78  249 kOhm  [RESC3216X65N]
RT79  249 kOhm  [RESC3216X65N]
RT80  249 kOhm  [RESC3216X65N]
RT81  249 kOhm  [RESC3216X65N]
RT87  4.99k  [RESC1608X55N]
RT88  1.8 kOhm  [RESC1608X55N]
RT90  4.99k  [RESC1608X55N]
RT93  1.8 kOhm  [RESC1608X55N]
RT94  249 kOhm  [RESC3216X65N]
RT95  249 kOhm  [RESC3216X65N]
RT96  249 kOhm  [RESC3216X65N]
RT97  249 kOhm  [RESC3216X65N]
RT98  249 kOhm  [RESC3216X65N]
RT99  249 kOhm  [RESC3216X65N]
UT1  AD8615AUJZ-REEL7  [sot23-5_0_95x2_70p_h1_22]
UT2  AD8615AUJZ-REEL7  [sot23-5_0_95x2_70p_h1_22]
UT12  AD8615AUJZ-REEL7  [sot23-5_0_95x2_70p_h1_22]
UT18  AD8615AUJZ-REEL7  [sot23-5_0_95x2_70p_h1_22]

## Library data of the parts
CB14 CB16 CB19 CT1 CT4 CT7-CT13 CT30 CT35 CT37 CT39 CT44-CT46 CT48-CT50 CT60 CT61 CT65 CT66 = CAP: CAP CER 0.1UF 25V X7R 0603; CLASS: DISCRETE; Company Part Status: New; Dielectric Type: Capacitors; Manufacturer: Kemet; Manufacturer PN: C0603C104K3RACTU; PART_NUMBER: TMP-847; Package Size: 0603 (1608 Metric); Rated Voltage: 25V; Temperature Coefficient: X7R; Tolerance: 10%
CT47 CT62 CT63 CT68 CT70 CT86 = CAP: CAP CER 10UF 25V X7S 0805; CLASS: DISCRETE; Company Part Status: New; Dielectric Type: Capacitors; Manufacturer: Murata Electronics North America; Manufacturer PN: GRM21BC71E106KE11L; PART_NUMBER: TMP-1080; Package Size: 0805 (2012 Metric); Rated Voltage: 25V; Temperature Coefficient: X7S; Tolerance: 10%
J9 = DSUB_-_NI_CAN_Interface_0: CONN D-SUB PLUG 9POS R/A SOLDER; CLASS: IO; Company Part Status: New; Manufacturer: Assmann WSW Components; PART_NUMBER: TMP-1302
RB27-RB30 RT50 RT108 RT113 RT115 RT118 RT127 = R: RES SMD 120 OHM 5% 1/10W 0603; CLASS: DISCRETE; Company Part Status: New; Manufacturer: Yageo; Manufacturer PN: RC0603JR-07120RL; PART_NUMBER: TMP-619; Package Size: 0603 (1608 Metric); Rated Power: 0.1W, 1/10W; Temperature Coefficient: 100ppm/C; Tolerance: 5%
UT11 = ISO1050DUB: IC TXRX CAN 5V 8SOP; CLASS: IC; Company Part Status: New; Manufacturer: Texas Instruments; PART_NUMBER: TMP-237; Package Size: 8-SMD, Gull Wing; Supply Voltage: 3 V - 5.5 V
UT17 = R1se-0505-R: DC/DC CONVERTER 1W 5VIN 5VOUT; CLASS: IC; Company Part Status: New; Manufacturer: Recom Power; PART_NUMBER: TMP-302; Package Size: 0.50" L x 0.42" W x 0.26" H (12.8mm x 10.7mm x 6.7mm)
CB5-CB12 CT14 CT31-CT33 = CAP: CAP CER 4700PF 25V X7R 0603; CLASS: DISCRETE; Company Part Status: New; Dielectric Type: Capacitors; Manufacturer: Murata Electronics North America; Manufacturer PN: GCM188R71E472KA37D; PART_NUMBER: TMP-889; Package Size: 0603 (1608 Metric); Rated Voltage: 25V; Temperature Coefficient: X7R; Tolerance: 10%
CB20-CB23 CT19-CT22 CT27-CT29 CT34 CT43 CT59 CT64 CT67 CT69 CT77 = CAP: CAP CER 100PF 50V 5% NP0 0603; CLASS: DISCRETE; Company Part Status: New; Dielectric Type: Capacitors; Manufacturer: Samsung Electro-Mechanics America, Inc; Manufacturer PN: CL10C101JB8NNNC; PART_NUMBER: TMP-455; Package Size: 0603 (1608 Metric); Rated Voltage: 50V; Temperature Coefficient: C0G, NP0; Tolerance: 5%
J4-J6 = CON3: CONN HEADER 3POS .100 VERT TIN; CLASS: IO; Company Part Status: New; Manufacturer: Molex, LLC; PART_NUMBER: TMP-626; Package Size: 0.295" (7.49mm)
RT15-RT21 RT23-RT27 = RES: RES SMD 49.9 OHM 1% 1/10W 0603; CLASS: DISCRETE; Company Part Status: New; Manufacturer: Panasonic Electronic Components; Manufacturer PN: ERJ-3EKF49R9V; PART_NUMBER: TMP-1252; Package Size: 0603 (1608 Metric); Rated Power: 0.1W, 1/10W; Temperature Coefficient: 100ppm/C; Tolerance: 1%
RT36 RT72-RT74 = RES: RES SMD 27 OHM 0.5% 1W 1206; CLASS: DISCRETE; Company Part Status: New; Manufacturer: Susumu; Manufacturer PN: HRG3216Q-27R0-D-T1; PART_NUMBER: TMP-1525; Package Size: 1206 (3216 Metric); Rated Power: 1W; Temperature Coefficient: 50ppm/C; Tolerance: 0.5%
RT37 RT51 RT53 RT55 = R: RES SMD 4.02KOHM 0.1% 1/10W 0603; CLASS: DISCRETE; Company Part Status: New; Manufacturer: Panasonic Electronic Components; Manufacturer PN: ERA-3AEB4021V; PART_NUMBER: TMP-1503; Package Size: 0603 (1608 Metric); Rated Power: 0.1W, 1/10W; Temperature Coefficient: 25ppm/C; Tolerance: 0.1%
RB19 RB20 RT38 RT62 RT64 RT66 = RES: RES SMD 2K OHM 1% 1/10W 0603; CLASS: DISCRETE; Company Part Status: New; Manufacturer: Yageo; Manufacturer PN: RC0603FR-072KL; PART_NUMBER: TMP-1519; Package Size: 0603 (1608 Metric); Rated Power: 0.1W, 1/10W; Temperature Coefficient: 100ppm/C; Tolerance: 1%
RT39 RT52 RT54 RT56 = R: RES 7.15K OHM 1% 1/10W 0603; CLASS: DISCRETE; Company Part Status: New; Manufacturer: Stackpole Electronics Inc.; Manufacturer PN: RMCF0603FT7K15; PART_NUMBER: TMP-1504; Package Size: 0603 (1608 Metric); Rated Power: 0.1W, 1/10W; Temperature Coefficient: 100ppm/C; Tolerance: 1%
RT49 RT63 RT65 RT67 = R: RES 1.33K OHM 1% 1/10W 0603; CLASS: DISCRETE; Company Part Status: New; Manufacturer: Stackpole Electronics Inc.; Manufacturer PN: RMCF0603FT1K33; PART_NUMBER: TMP-1506; Package Size: 0603 (1608 Metric); Rated Power: 0.1W, 1/10W; Temperature Coefficient: 100ppm/C; Tolerance: 1%
RT57 RT59-RT61 = R: RES SMD 7.87K OHM 1% 1/10W 0603; CLASS: DISCRETE; Company Part Status: New; Manufacturer: Yageo; Manufacturer PN: RC0603FR-077K87L; PART_NUMBER: TMP-1505; Package Size: 0603 (1608 Metric); Rated Power: 0.1W, 1/10W; Temperature Coefficient: 100ppm/C; Tolerance: 1%
UT1-UT10 UT12 UT18 = AD8615: IC OPAMP GP 24MHZ RRO TSOT23-5; CLASS: IC; Company Part Status: New; Manufacturer: Analog Devices Inc.; PART_NUMBER: TMP-1499; Package Size: SOT-23-5 Thin, TSOT-23-5; Supply Voltage: 2.7 V - 5.5 V, 1.35 V - 2.75 V
CT52 CT53 CT55-CT58 = CAP: CAP CER 27PF 50V NP0 0603; CLASS: DISCRETE; Company Part Status: New; Dielectric Type: Capacitors; Manufacturer: Samsung Electro-Mechanics America, Inc.; Manufacturer PN: CL10C270JB8NNNC; PART_NUMBER: TMP-759; Package Size: 0603 (1608 Metric); Rated Voltage: 50V; Temperature Coefficient: C0G, NP0; Tolerance: 5%
J1-J3 = CON16A_Corrected: CONN HEADER 2.54MM 16POS GOLD; CLASS: IO; Company Part Status: New; Manufacturer: Sullins Connector Solutions; PART_NUMBER: TMP-739
LT1-LT12 = INDUCTOR: FIXED IND 1UH 1.15A 60 MOHM SMD; CLASS: DISCRETE; Company Part Status: New; Manufacturer: TDK Corporation; Manufacturer PN: MLZ2012N1R0LT000; PART_NUMBER: TMP-610; Package Size: 0805 (2012 Metric); Tolerance: 20%
RT89 RT100 RT101 RT106 RT111 RT112 RT114 RT120 = R: RES SMD 15K OHM 5% 1/10W 0603; CLASS: DISCRETE; Company Part Status: New; Manufacturer: Yageo; Manufacturer PN: RC0603JR-0715KL; PART_NUMBER: TMP-618; Package Size: 0603 (1608 Metric); Rated Power: 0.1W, 1/10W; Temperature Coefficient: 100ppm/C; Tolerance: 5%
RT91 RT92 RT102-RT105 = RES: RES SMD 100 OHM 1% 1/10W 0603; CLASS: DISCRETE; Company Part Status: New; Manufacturer: Yageo; Manufacturer PN: RC0603FR-07100RL; PART_NUMBER: TMP-865; Package Size: 0603 (1608 Metric); Rated Power: 0.1W, 1/10W; Temperature Coefficient: 100ppm/C; Tolerance: 1%
UT19 UT20 = DIFFRCVR_4XG_16P: IC RCVR DIFF QUAD LV HS 16TSSOP; CLASS: IC; Company Part Status: New; Manufacturer: Texas Instruments; PART_NUMBER: TMP-1495; Package Size: 16-TSSOP (0.173", 4.40mm Width); Supply Voltage: 3 V - 3.6 V
UT22 = 74-541_20P: IC BUF NON-INVERT 5.5V 20TSSOP; CLASS: IC; Company Part Status: New; Digikey: 296-18698-1-ND; Manufacturer: Texas Instruments; PART_NUMBER: TMP-1497; Package Size: 20-TSSOP (0.173", 4.40mm Width); Supply Voltage: 4.5 V - 5.5 V
UT23 = 74-541_20P: IC BUF NON-INVERT 5.5V 20TSSOP; CLASS: IC; Company Part Status: New; Manufacturer: Texas Instruments; PART_NUMBER: TMP-1497; Package Size: 20-TSSOP (0.173", 4.40mm Width); Supply Voltage: 4.5 V - 5.5 V
UT24 UT25 = DIFFDRVR_4X_16P: IC DVR DIFF QUAD LV HS 16TSSOP; CLASS: IC; Company Part Status: New; Manufacturer: Texas Instruments; PART_NUMBER: TMP-1494; Package Size: 16-TSSOP (0.173", 4.40mm Width); Supply Voltage: 3 V - 3.6 V
DT1 = LED_0: LED RED DIFFUSED 0805 SMD; CLASS: DISCRETE; Company Part Status: New; Manufacturer: OSRAM Opto Semiconductors Inc.; PART_NUMBER: TMP-917; Package Size: 0805 (2012 Metric); Rated Voltage: 1.8V @ 20mA
DT2 = LED_0: LED YELLOW CLEAR 0805 SMD; CLASS: DISCRETE; Company Part Status: New; Manufacturer: Lite-On Inc.; PART_NUMBER: TMP-656; Package Size: 0805 (2012 Metric)
DT3 = LED_0: LED GREEN DIFFUSED 0805 SMD; CLASS: DISCRETE; Company Part Status: New; Manufacturer: OSRAM Opto Semiconductors Inc.; PART_NUMBER: TMP-915; Package Size: 0805 (2012 Metric); Rated Voltage: 2.2V
DT6 DT7 = LED_-_Purple: Standard LEDs - SMD Violet Water Clear 250mcd 120 Deg; CLASS: DISCRETE; Company Part Status: Released; PART_NUMBER: TMP-147; Package Size: 3.5 mm x 2.8 mm x 1.9 mm
J10 = CONN_CENT_RCPT_26: CONN RCPT 26POS R/A SOLDER; CLASS: IO; Company Part Status: New; Manufacturer: 3M; PART_NUMBER: TMP-1512
RT11-RT13 = RES: RES SMD 680 OHM 1% 1/10W 0603; CLASS: DISCRETE; Company Part Status: New; Manufacturer: Yageo; Manufacturer PN: RC0603FR-07680RL; PART_NUMBER: TMP-1267; Package Size: 0603 (1608 Metric); Rated Power: 0.1W, 1/10W; Temperature Coefficient: 100ppm/C; Tolerance: 1%
RT82 RT107 RT117 RT122-RT124 RT130 RT131 = R: RES SMD 10K OHM 1% 1/10W 0603; CLASS: DISCRETE; Company Part Status: New; Manufacturer: Rohm Semiconductor; Manufacturer PN: MCR03ERTF1002; PART_NUMBER: TMP-380; Package Size: 0603 (1608 Metric); Rated Power: 0.1W, 1/10W; Temperature Coefficient: 100ppm/C; Tolerance: 1%
RT116 RT119 = R: RES 1.8K OHM 1/8W 1% 0805 SMD; CLASS: DISCRETE; Manufacturer: Rohm Semiconductor; Manufacturer PN: KTR10EZPF1801; PART_NUMBER: TMP-277; Package Size: 0805 (2012 Metric); Rated Power: 0.125W, 1/8W; Temperature Coefficient: 100ppm/C; Tolerance: 1%
UB3 = AND3_1X_6PIN: IC GATE AND 1CH 3-INP SOT23-6; CLASS: IC; Company Part Status: New; Manufacturer: Texas Instruments; PART_NUMBER: TMP-1521; Package Size: SOT-23-6; Supply Voltage: 1.65 V - 5.5 V
UT13 = F28379D-launchpad
UT21 UT28 UT30 = MOSFET_N_GSD: MOSFET N-CH 50V 0.2A SOT-23; CLASS: DISCRETE; Company Part Status: Released; Manufacturer: ON Semiconductor; PART_NUMBER: TMP-1374; Package Size: TO-236-3, SC-59, SOT-23-3; Polarity: N-Channel; Rated Power: 350mW
CB13 CB15 CT5 CT6 CT15-CT17 CT23-CT26 CT36 CT38 CT40-CT42 CT51 CT54 = CAP: CAP CER 10000PF 25V 10% X7R 0603; CLASS: DISCRETE; Company Part Status: New; Dielectric Type: Capacitors; Manufacturer: Samsung Electro-Mechanics America, Inc.; Manufacturer PN: CL10B103KA8NNNC; PART_NUMBER: TMP-566; Package Size: 0603 (1608 Metric); Rated Voltage: 25V; Temperature Coefficient: X7R; Tolerance: 10%
CB17 CB18 = CAP: CAP CER 10UF 6.3V X7R 0603; CLASS: DISCRETE; Company Part Status: New; Dielectric Type: Capacitors; Manufacturer: Samsung Electro-Mechanics America, Inc.; Manufacturer PN: CL10B106MQ8NRNC; PART_NUMBER: TMP-1114; Package Size: 0603 (1608 Metric); Rated Voltage: 6.3V; Temperature Coefficient: X7R; Tolerance: 20%
CT71 CT75 = CAP: CAP CER 1000PF 50V X7R 0603; CLASS: DISCRETE; Dielectric Type: Capacitors; Manufacturer: TDK Corporation; Manufacturer PN: CGA3E2X7R1H102K080AA; PART_NUMBER: TMP-887; Package Size: 0603 (1608 Metric); Temperature Coefficient: X7R; Tolerance: 10%
CT72 CT76 CT81 CT85 = CAP: CAP CER 10UF 25V X7R 1206; CLASS: DISCRETE; Company Part Status: Released; Dielectric Type: Capacitors; Manufacturer: Samsung Electro-Mechanics; Manufacturer PN: CL31B106KAHNNNE; PART_NUMBER: TMP-1386; Package Size: 1206 (3216 Metric); Rated Voltage: 25V; Temperature Coefficient: X7R; Tolerance: 10%
CT73 CT79 = CAP: CAP CER 56PF 50V C0G/NP0 0603; CLASS: DISCRETE; Company Part Status: Released; Dielectric Type: Capacitors; Manufacturer: Samsung Electro-Mechanics; Manufacturer PN: CL10C560JB8NNNC; PART_NUMBER: TMP-1515; Package Size: 0603 (1608 Metric); Rated Voltage: 50V; Temperature Coefficient: C0G, NP0; Tolerance: 5%
CT74 CT80 = CAP: CAP CER 0.1UF 50V X7R 0603; CLASS: DISCRETE; Company Part Status: Released; Dielectric Type: Capacitors; Manufacturer: Yageo; Manufacturer PN: CC0603KRX7R9BB104; PART_NUMBER: TMP-1516; Package Size: 0603 (1608 Metric); Rated Voltage: 50V; Temperature Coefficient: X7R; Tolerance: 10%
CT78 CT83 CT84 = CAP: CAP CER 4.7UF 50V 10% X7R 1206; CLASS: DISCRETE; Dielectric Type: Ceramic; Manufacturer: Taiyo Yuden; Manufacturer PN: UMK316AB7475KL-T; PART_NUMBER: TMP-119; Package Size: 1206 (3216 Metric); Rated Voltage: 50V; Temperature Coefficient: X7R; Tolerance: ±10%
CT82 = CAP: CAP CER 1UF 50V 10% X7R 0805; CLASS: DISCRETE; Company Part Status: New; Dielectric Type: Capacitors; Manufacturer: Samsung Electro-Mechanics America, Inc; Manufacturer PN: CL21B105KBFNNNE; PART_NUMBER: TMP-453; Package Size: 0805 (2012 Metric); Rated Voltage: 50V; Temperature Coefficient: X7R; Tolerance: 10%
CT2 CT3 CT18 CT87 = CAP: CAP CER 4700PF 25V X7R 0603; CLASS: DISCRETE; Dielectric Type: Capacitors; Manufacturer: Murata Electronics North America; Manufacturer PN: GCM188R71E472KA37D; PART_NUMBER: TMP-889; Package Size: 0603 (1608 Metric); Temperature Coefficient: X7R; Tolerance: 10%
CT88 = CAP: CAP CER 0.022UF 50V X7R 0805; CLASS: DISCRETE; Company Part Status: New; Dielectric Type: Ceramic; Manufacturer: Yageo; Manufacturer PN: CC0805KRX7R9BB223; PART_NUMBER: TMP-667; Package Size: 0805 (2012 Metric); Rated Voltage: 50V; Temperature Coefficient: X7R; Tolerance: 10%
DT4 DT5 DT11 DT12 = LED_0: LED GREEN CLEAR 0805 SMD; CLASS: DISCRETE; Company Part Status: Released; Manufacturer: Lite-On Inc.; PART_NUMBER: TMP-1003; Package Size: 0805 (2012 Metric)
DT8 DT9 = DIODE_SCHOTTKY_0: DIODE SCHOTTKY 60V 2A SOD123FL; CLASS: DISCRETE; Company Part Status: New; Manufacturer: ON Semiconductor; PART_NUMBER: TMP-1369; Package Size: SOD-123F; Rated Voltage: 60 V
DT10 = DIODE_SCHOTTKY_C2_A1_0: DIODE SCHOTTKY 30V 200MA; CLASS: DISCRETE; Company Part Status: Released; Manufacturer: Toshiba Semiconductor and Storage; PART_NUMBER: TMP-880; Package Size: SC-76, SOD-323; Rated Voltage: 280mV @ 10mA
J11 = power_jack: CONN PWR JACK 2X5.5MM SOLDER; CLASS: IO; Company Part Status: New; Manufacturer: CUI Inc.; PART_NUMBER: TMP-1599
J12 J13 = 1x2_100mil: CONN HEADER VERT 2POS .100 TIN; CLASS: IO; Company Part Status: New; Manufacturer: TE Connectivity AMP Connectors; PART_NUMBER: TMP-943; Package Size: 0.295" (7.49mm)
LT13 = Coupled_Inductor: Part Number: MSD7342-682MLC
LT14 = IND: FIXED IND 3.3UH 3.3A 27 MOHM SMD; CLASS: DISCRETE; Company Part Status: New; Manufacturer: Taiyo Yuden; Manufacturer PN: NRS5040T3R3NMGJ; PART_NUMBER: TMP-1594; Package Size: Nonstandard; Tolerance: 30%
QT1 = MOSFET_P_PSO8: MOSFET P-CH 60V 8.6A PPAK SO-8; CLASS: DISCRETE; Company Part Status: New; Manufacturer: Vishay Siliconix; Manufacturer PN: SI7461DP-T1-E3; PART_NUMBER: TMP-1595; Package Size: PowerPAK® SO-8; Polarity: P-Channel; Rated Power: 1.9W (Ta)
QT2 QT3 = MOSFET_N_PSO8: MOSFET N-CHA 60V 17.9A POWERDI; CLASS: DISCRETE; Company Part Status: New; Manufacturer: Diodes Incorporated; PART_NUMBER: TMP-1530; Package Size: 8-PowerTDFN; Polarity: N-Channel; Rated Power: 2.6 W
RT109 = R: RES SMD 499 OHM 1% 1/8W 0805; CLASS: DISCRETE; Company Part Status: New; Manufacturer: Rohm Semiconductor; Manufacturer PN: MCR10ERTF4990; PART_NUMBER: TMP-897; Package Size: 0805 (2012 Metric); Rated Power: 0.125W, 1/8W; Temperature Coefficient: 100ppm/C; Tolerance: 1%
RT110 = R: RES SMD 249 OHM 1% 1/8W 0805; CLASS: DISCRETE; Company Part Status: New; Manufacturer: Rohm Semiconductor; Manufacturer PN: MCR10ERTF2490; PART_NUMBER: TMP-488; Package Size: 0805 (2012 Metric); Rated Power: 0.125W, 1/8W; Temperature Coefficient: 100ppm/C; Tolerance: 1%
RT121 = R: CRGCQ 0603 180K 1%; CLASS: DISCRETE; Company Part Status: New; Manufacturer: TE Connectivity Passive Product; Manufacturer PN: CRGCQ0603F180K; PART_NUMBER: TMP-1539; Package Size: 0603 (1608 Metric); Rated Power: 0.1W, 1/10W; Temperature Coefficient: 100ppm/C; Tolerance: 1%
RT125 RT133 RT135 RT136 RT142 = R: RES SMD 100K OHM 1% 1/10W 0603; CLASS: DISCRETE; Company Part Status: New; Manufacturer: Rohm Semiconductor; Manufacturer PN: MCR03ERTF1003; PART_NUMBER: TMP-382; Package Size: 0603 (1608 Metric); Rated Power: 0.1W, 1/10W; Temperature Coefficient: 100ppm/C; Tolerance: 1%
RT126 RT134 = RES: RES 45.3K OHM 1% 1/10W 0603; CLASS: DISCRETE; Company Part Status: New; Manufacturer: Stackpole Electronics Inc; Manufacturer PN: RMCF0603FT45K3; PART_NUMBER: TMP-1597; Package Size: 0603 (1608 Metric); Rated Power: 0.1W, 1/10W; Temperature Coefficient: 100ppm/C; Tolerance: 1%
RT128 RT132 = R: RES SMD 56K OHM 1% 1/10W 0603; CLASS: DISCRETE; Company Part Status: New; Manufacturer: Yageo; Manufacturer PN: RC0603FR-0756KL; PART_NUMBER: TMP-614; Package Size: 0603 (1608 Metric); Rated Power: 0.1W, 1/10W; Temperature Coefficient: 100ppm/C; Tolerance: 1%
RT129 = RES: RES SMD 165K OHM 0.1% 1/10W 0603; CLASS: DISCRETE; Company Part Status: New; Manufacturer: Panasonic Electronic Components; Manufacturer PN: ERA-3AEB1653V; PART_NUMBER: TMP-1598; Package Size: 0603 (1608 Metric); Rated Power: 0.1W, 1/10W; Temperature Coefficient: 25ppm/C; Tolerance: 0.1%
RT137 RT138 = R: RES SMD 2.43K OHM 1% 1/8W 0805; CLASS: DISCRETE; Company Part Status: New; Manufacturer: Panasonic Electronic Components; Manufacturer PN: ERJ-6ENF2431V; PART_NUMBER: TMP-1119; Package Size: 0805 (2012 Metric); Rated Power: 0.125W, 1/8W; Temperature Coefficient: 100ppm/C; Tolerance: 1%
RT139 = R: RES SMD 22K OHM 1% 1/10W 0603; CLASS: DISCRETE; Manufacturer: Panasonic Electronic Components; Manufacturer PN: ERJ-3EKF2202V; PART_NUMBER: TMP-786; Package Size: 0603 (1608 Metric); Rated Power: 0.1W, 1/10W; Temperature Coefficient: 100ppm/C; Tolerance: 1%
RT140 = R: RES SMD 200K OHM 1% 1/10W 0603; CLASS: DISCRETE; Company Part Status: New; Manufacturer: Panasonic Electronic Components; Manufacturer PN: ERJ-3EKF2003V; PART_NUMBER: TMP-1536; Package Size: 0603 (1608 Metric); Rated Power: 0.1W, 1/10W; Temperature Coefficient: 100ppm/C; Tolerance: 1%
RT141 = RES: RES 0.01 OHM 1% 2W 2512; CLASS: DISCRETE; Company Part Status: New; Manufacturer: Yageo; Manufacturer PN: PE2512FKE7W0R01L; PART_NUMBER: TMP-1531; Package Size: 2512 (6432 Metric); Rated Power: 2W; Temperature Coefficient: 50ppm/C; Tolerance: 1%
RT143 RT144 = R: RES SMD 2.7M OHM 5% 1/10W 0603; CLASS: DISCRETE; Company Part Status: New; Manufacturer: Yageo; Manufacturer PN: RC0603JR-072M7L; PART_NUMBER: TMP-1537; Package Size: 0603 (1608 Metric); Rated Power: 0.1W, 1/10W; Temperature Coefficient: 100ppm/C; Tolerance: 5%
UB1 = REF3312AIDCKR_-_Vref_0: IC VREF SERIES 1.5V SOT-23-3; CLASS: IC; Manufacturer: Intersil; PART_NUMBER: TMP-150; Package Size: TO-236-3, SC-59, SOT-23-3
UB2 = REF3312AIDCKR_-_Vref_0: IC VREF SERIES 3V SOT23-3; CLASS: IC; Company Part Status: New; Manufacturer: Renesas Electronics America Inc.; PART_NUMBER: TMP-1526; Package Size: TO-236-3, SC-59, SOT-23-3
UT26 = LM7805: DC DC CONVERTER 5V 5W; CLASS: IC; Company Part Status: New; Manufacturer: Recom Power; PART_NUMBER: TMP-1517; Package Size: 0.46" L x 0.33" W x 0.41" H (11.6mm x 8.5mm x 10.4mm); Rated Power: 5 W
UT27 = LM7805: DC DC CONVERTER 3.3V 3W; CLASS: IC; Company Part Status: New; Manufacturer: Recom Power; PART_NUMBER: TMP-1518; Package Size: 0.46" L x 0.33" W x 0.41" H (11.6mm x 8.5mm x 10.4mm); Rated Power: 3.3 W
UT29 UT31 = LT3581: IC REG MULTI CONFG ADJ 16MSOP; CLASS: IC; Company Part Status: New; Manufacturer: Linear Technology/Analog Devices; Manufacturer PN: LT3581EMSE#PBF; PART_NUMBER: TMP-1596; Package Size: 16-TFSOP (0.118", 3.00mm Width) Exposed Pad
UT32 = LTC4368: IC SURGE SUPPRESSION ADJ 10MSOP; CLASS: IC; Company Part Status: New; Manufacturer: Linear Technology/Analog Devices; PART_NUMBER: TMP-1529; Package Size: 10-MSOP (0.118", 3.00mm Width); Supply Voltage: 2.5 - 60 V
RT41-RT47 = RES: RES SMD 30.1K OHM 1% 1/10W 0603; CLASS: DISCRETE; Company Part Status: New; Manufacturer: Panasonic Electronic Components; Manufacturer PN: ERJ-3EKF3012V; PART_NUMBER: TMP-962; Package Size: 0603 (1608 Metric); Rated Power: 0.1W, 1/10W; Temperature Coefficient: 100ppm/C; Tolerance: 1%
RT48 = RES: RES SMD 17.8K OHM 1% 1/10W 0603; CLASS: DISCRETE; Company Part Status: Released; Manufacturer: Panasonic Electronic Components; Manufacturer PN: ERJ-3EKF1782V; PART_NUMBER: TMP-995; Package Size: 0603 (1608 Metric); Rated Power: 0.1W, 1/10W; Temperature Coefficient: 100ppm/C; Tolerance: 1%
RT69-RT71 = RES: RES SMD 2.2K OHM 1% 1/10W 0603; CLASS: DISCRETE; Company Part Status: New; Manufacturer: Yageo; Manufacturer PN: RC0603FR-072K2L; PART_NUMBER: TMP-1308; Package Size: 0603 (1608 Metric); Rated Power: 0.1W, 1/10W; Temperature Coefficient: 100ppm/C; Tolerance: 1%
RT83 = PTC: THERMISTOR NTC 10KOHM 3900K 0805; CLASS: DISCRETE; Company Part Status: New; Manufacturer: Murata Electronics North America; Manufacturer PN: NCP21XV103J03RA; PART_NUMBER: TMP-1511; Package Size: 0805 (2012 Metric); Rated Power: 200mW; Temperature Coefficient: 3900K; Tolerance: 5%
RT84-RT86 = RES: RES SMD 0 OHM JUMPER 1/8W 0805; CLASS: DISCRETE; Company Part Status: Released; Manufacturer: Samsung Electro-Mechanics; Manufacturer PN: RC2012J000CS; PART_NUMBER: TMP-1398; Package Size: 0805 (2012 Metric); Rated Power: 0.125W, 1/8W; Tolerance: Jumper
UT14-UT16 = 74LVC123: IC SNGLE MONO MULTIVBTOR US8; CLASS: IC; Company Part Status: New; Manufacturer: Texas Instruments; Manufacturer PN: SN74LVC1G123DCUR; PART_NUMBER: TMP-1593; Package Size: 8-VFSOP (0.091", 2.30mm Width); Supply Voltage: 1.65V ~ 5.5V
CB1-CB4 = CAP: CAP CER 0.27UF 16V X7R 0603; CLASS: DISCRETE; Company Part Status: New; Dielectric Type: Capacitors; Manufacturer: Murata Electronics North America; Manufacturer PN: GCM188R71C274KA37D; PART_NUMBER: TMP-1544; Package Size: 0603 (1608 Metric); Rated Voltage: 16V; Temperature Coefficient: X7R; Tolerance: 10%
J7 = HDR_1X6_M: TERM BLK 6POS SIDE ENT 7.5MM PCB; CLASS: IO; Company Part Status: New; Contact Voltage: 1000 V; Manufacturer: Phoenix Contact; PART_NUMBER: TMP-1496
J8 = CON2
RB1-RB18 RB21-RB26 RT5-RT10 RT30-RT35 RT76-RT81 RT94-RT99 = RES: RES 249K OHM 0.1% 2/5W 1206; CLASS: DISCRETE; Company Part Status: New; Manufacturer: Vishay Dale; Manufacturer PN: TNPW1206249KBEEA; PART_NUMBER: TMP-1522; Package Size: 1206 (3216 Metric); Rated Power: 0.4W, 2/5W; Temperature Coefficient: 25ppm/C; Tolerance: 0.1%
RT1 RT3 RT14 RT28 RT40 RT68 RT87 RT90 = RES: RES SMD 4.99K OHM 1% 1/10W 0603; CLASS: DISCRETE; Company Part Status: Released; Manufacturer: Yageo; Manufacturer PN: RC0603FR-074K99L; PART_NUMBER: TMP-871; Package Size: 0603 (1608 Metric); Rated Power: 0.1W, 1/10W; Temperature Coefficient: 100ppm/C; Tolerance: 1%
RT2 RT4 = RES: RES SMD 3.74K OHM 0.1% 1/5W 0603; CLASS: DISCRETE; Company Part Status: New; Manufacturer: Panasonic Electronic Components; Manufacturer PN: ERJ-PB3B3741V; PART_NUMBER: TMP-1543; Package Size: 0603 (1608 Metric); Rated Power: 0.2W, 1/5W; Temperature Coefficient: 50ppm/C; Tolerance: 0.1%
RT22 RT29 RT58 RT75 RT88 RT93 = RES: RES SMD 1.8K OHM 0.1% 1/5W 0603; CLASS: DISCRETE; Company Part Status: New; Manufacturer: Panasonic Electronic Components; Manufacturer PN: ERJ-PB3B1801V; PART_NUMBER: TMP-1523; Package Size: 0603 (1608 Metric); Rated Power: 0.2W, 1/5W; Temperature Coefficient: 50ppm/C; Tolerance: 0.1%

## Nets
+1V5REF: CB13.1 RB19.1 RT29.1 RT75.1 RT93.1 UB1.2(OUT)
+3V3: CB14.1 CB16.1 CB19.1 CT1.1 CT4.1 CT7.1 CT8.1 CT9.1 CT10.1 CT11.1 CT12.1 CT13.1 CT30.1 CT35.1 CT39.1 CT44.1 CT45.1 CT46.1 CT48.1 CT49.1 CT50.1 CT60.1 CT61.1 CT62.1 J10.10 RT69.1 RT70.1 RT71.1 RT83.2 RT100.1 RT106.1 RT110.1 RT112.1 RT120.1 UB1.1(IN) UB2.1(IN) UB3.5(VCC) UT1.5(V+) UT2.5(V+) UT3.5(V+) UT4.5(V+) UT5.5(V+) UT6.5(V+) UT7.5(V+) UT8.5(V+) UT9.5(V+) UT10.5(V+) UT11.1(Vcc1) UT12.5(V+) UT13.1(3V3) UT13.41(3V3_2) UT13.102(3V3_3) UT14.3(~{CLR}) UT14.8(VCC) UT15.3(~{CLR}) UT15.8(VCC) UT16.3(~{CLR}) UT16.8(VCC) UT18.5(V+) UT19.16(VCC) UT20.16(VCC) UT24.16(VCC) UT25.16(VCC) UT27.3(Output)
+3VREF: CB15.1 RB20.1 RT49.1 RT63.1 RT65.1 RT67.1 UB2.2(OUT)
+5V: CT63.1 CT65.1 CT66.1 J10.12 J10.20 RT109.1 UT13.21(5V_1) UT13.61(5V_2) UT13.92(5V_3) UT13.97(5V_4) UT13.105(5V_5) UT17.2(+VIN) UT22.20(VCC) UT23.20(VCC) UT26.3(Output)
+5V-ISO: CT37.1 CT47.1 J9.9(V+) UT11.8(Vcc2) UT17.5(+VOUT)
+12V: CT68.1 CT70.1 CT78.1 CT83.1 CT86.1 DT10.A(ANODE) J1.1 J2.1 J3.1 J12.1 J13.1 LT13.1 LT14.1 RT116.1 RT119.1 RT125.1 RT128.2 RT132.2 RT133.1 RT141.2 UT26.1(Input) UT27.1(Input) UT29.5(VIN) UT31.5(VIN) UT32.8(VOUT)
+15V: CT72.1 CT85.1 J4.1 J5.1 J6.1 J10.8 QT1.5(D) RT138.1
-15V: CT76.1 CT81.1 DT11.2(C) J4.3 J5.3 J6.3 J10.7 LT13.2 RT121.2
VIN: J11.1(Vin) QT2.5(D) RT136.1 RT144.1 UT32.1(VIN)
0: CB1.2 CB2.2 CB3.2 CB4.2 CB5.2 CB6.2 CB7.2 CB8.2 CB9.2 CB10.2 CB11.2 CB12.2 CB13.2 CB14.2 CB15.2 CB16.2 CB17.2 CB18.2 CB19.2 CB20.2 CB21.2 CB22.2 CB23.2 CT1.2 CT3.1 CT4.2 CT6.1 CT7.2 CT8.2 CT9.2 CT10.2 CT11.2 CT12.2 CT13.2 CT14.2 CT15.1 CT16.1 CT17.1 CT18.1 CT19.2 CT20.2 CT21.2 CT22.2 CT30.2 CT31.2 CT32.2 CT33.2 CT35.2 CT38.1 CT39.2 CT43.1 CT44.2 CT45.2 CT46.2 CT48.2 CT49.2 CT50.2 CT54.1 CT59.2 CT60.2 CT61.2 CT62.2 CT63.2 CT64.2 CT65.2 CT66.2 CT67.2 CT68.2 CT69.2 CT70.2 CT71.2 CT72.2 CT73.1 CT74.1 CT75.2 CT76.2 CT77.2 CT78.2 CT79.1 CT80.1 CT81.2 CT83.2 CT84.2 CT85.2 CT86.2 CT87.2 CT88.2 DT1.2(C) DT2.2(C) DT3.2(C) DT4.2(C) DT5.2(C) DT8.1(C) DT12.2(C) J1.2 J1.12 J1.14 J1.16 J2.2 J2.12 J2.14 J2.16 J3.2 J3.12 J3.14 J3.16 J10.3 J10.4 J10.5 J10.9 J10.11 J10.13 J10.15 J10.17 J10.19 J10.21 J10.23 J10.25 J11.2(GND) J11.3(GND.) J12.2 J13.2 RT4.1 RT36.2 RT37.1 RT51.1 RT53.1 RT55.1 RT72.2 RT73.2 RT74.2 RT82.1 RT89.2 RT101.2 RT107.2 RT111.1 RT114.1 RT117.2 RT123.2 RT124.2 RT126.1 RT131.2 RT134.1 RT137.1 RT140.2 UB1.3(GND) UB2.3(GND) UB3.2(GND) UT1.2(V-) UT2.2(V-) UT3.2(V-) UT4.2(V-) UT5.2(V-) UT6.2(V-) UT7.2(V-) UT8.2(V-) UT9.2(V-) UT10.2(V-) UT11.4(GND1) UT12.2(V-) UT13.20(GND2) UT13.22(GND1) UT13.60(GND3) UT13.62(GND4) UT13.82(GND5) UT13.84(GND6) UT13.86(GND7) UT13.88(GND8) UT13.93(GND9) UT13.98(GND10) UT13.101(GND11) UT13.103(GND12) UT13.104(GND13) UT13.106(GND14) UT13.107(GND15) UT14.1(~{A}) UT14.4(GND) UT15.1(~{A}) UT15.4(GND) UT16.1(~{A}) UT16.4(GND) UT17.1(-VIN) UT18.2(V-) UT19.8(GND) UT20.8(GND) UT21.2(S) UT22.1(OE1) UT22.2(A1) UT22.3(A2) UT22.10(GND) UT22.19(OE2) UT23.1(OE1) UT23.5(A4) UT23.6(A5) UT23.7(A6) UT23.8(A7) UT23.9(A8) UT23.10(GND) UT23.19(OE2) UT24.8(GND) UT25.8(GND) UT26.2(Gnd) UT27.2(Gnd) UT28.2(S) UT29.16(SYNC) UT29.17(GND) UT30.2(S) UT31.16(SYNC) UT31.17(GND) UT32.5(GND)
1: CT37.2 CT47.2 J9.3(V-) J9.5(SHIELD) J9.10(shield1) J9.11(shield2) UT11.5(GND2) UT17.4(-VOUT)
A-Current: CB7.1 RT15.2 UT13.30(AA0)
A-FAULT: UB3.6(C) UT13.80(EPWM4A) UT19.3(Y1)
A-FAULT-N: J1.8 LT1.1
A-FAULT-N-Filter: CT52.2 LT1.2 RT91.2 UT19.1(B1)
A-FAULT-P: J1.7 LT3.1
A-FAULT-P-Filter: CT52.1 LT3.2 RT91.1 UT19.2(A1)
A-LEN: J1.13 UT22.12(Y7)
A-LEN-OUT: UT13.52(P27) UT22.8(A7)
A-OCEN: J1.15 UT22.11(Y8)
A-OCEN-OUT: UT13.51(P25) UT22.9(A8)
A-PSDIS: J1.11 UT23.16(Y3)
A-PSDIS-OUT: UT13.58(P131) UT23.4(A3)
A-RTD: RT84.1 UT13.46(P94) UT14.2(B) UT19.5(Y2)
A-RTD-N: J1.10 LT7.1
A-RTD-N-Filter: CT55.2 LT7.2 RT102.2 UT19.7(B2)
A-RTD-P: J1.9 LT5.1
A-RTD-P-Filter: CT55.1 LT5.2 RT102.1 UT19.6(A2)
A-TEMP: CB11.1 RT24.2 UT13.69(AA4)
AHS-PWM: RB28.1 UT13.40(EPWM1A)
AHS-PWM-N: J1.4 UT24.3(Z1)
AHS-PWM-P: J1.3 UT24.2(Y1)
ALS-PWM: RB29.1 UT13.39(EPWM1B)
ALS-PWM-N: J1.6 UT24.5(Z2)
ALS-PWM-P: J1.5 UT24.6(Y2)
B-Current: CB6.1 RT16.2 UT13.29(AA2)
B-FAULT: UB3.3(B) UT13.79(EPWM4B) UT19.11(Y3)
B-FAULT-N: J2.8 LT8.1
B-FAULT-N-Filter: CT56.2 LT8.2 RT103.2 UT19.9(B3)
B-FAULT-P: J2.7 LT6.1
B-FAULT-P-Filter: CT56.1 LT6.2 RT103.1 UT19.10(A3)
B-LEN: J2.13 UT22.14(Y5)
B-LEN-OUT: UT13.54(P64) UT22.6(A5)
B-OCEN: J2.15 UT22.13(Y6)
B-OCEN-OUT: UT13.53(P26) UT22.7(A6)
B-PSDIS: J2.11 UT23.17(Y2)
B-PSDIS-OUT: UT13.59(P66) UT23.3(A2)
B-RTD: RT85.1 UT13.45(P97) UT15.2(B) UT19.13(Y4)
B-RTD-N: J2.10 LT2.1
B-RTD-N-Filter: CT53.2 LT2.2 RT92.2 UT19.15(B4)
B-RTD-P: J2.9 LT4.1
B-RTD-P-Filter: CT53.1 LT4.2 RT92.1 UT19.14(A4)
B-TEMP: CB10.1 RT25.2 UT13.67(AC4)
BHS-PWM: RB30.1 UT13.38(EPWM2A)
BHS-PWM-N: J2.4 UT24.11(Z3)
BHS-PWM-P: J2.3 UT24.10(Y3)
BLS-PWM: RB27.1 UT13.37(EPWM2B)
BLS-PWM-N: J2.6 UT24.13(Z4)
BLS-PWM-P: J2.5 UT24.14(Y4)
C-Current: CB5.1 RT17.2 UT13.28(AB2)
C-FAULT: UB3.1(A) UT13.78(EPWM5A) UT20.3(Y1)
C-FAULT-N: J3.8 LT9.1
C-FAULT-N-Filter: CT57.2 LT9.2 RT104.2 UT20.1(B1)
C-FAULT-P: J3.7 LT10.1
C-FAULT-P-Filter: CT57.1 LT10.2 RT104.1 UT20.2(A1)
C-LEN: J3.13 UT22.16(Y3)
C-LEN-OUT: UT13.57(P130) UT22.4(A3)
C-OCEN: J3.15 UT22.15(Y4)
C-OCEN-OUT: UT13.55(P63) UT22.5(A4)
C-PSDIS: J3.11 UT23.18(Y1)
C-PSDIS-OUT: UT13.74(P14) UT23.2(A1)
C-RTD: RT86.1 UT13.42(P95) UT16.2(B) UT20.5(Y2)
C-RTD-N: J3.10 LT12.1
C-RTD-N-Filter: CT58.2 LT12.2 RT105.2 UT20.7(B2)
C-RTD-P: J3.9 LT11.1
C-RTD-P-Filter: CT58.1 LT11.2 RT105.1 UT20.6(A2)
C-TEMP: CB9.1 RT26.2 UT13.66(AA5)
CANA-H: J9.7(CAN_H) RT50.1 UT11.7(CANH)
CANA-L: J9.2(CAN_L) RT50.2 UT11.6(CANL)
CANA-RX: UT11.2(RXD) UT13.4(P18)
CANA-TX: UT11.3(TXD) UT13.3(P19)
CANBH: J10.2 UT13.99(CANH)
CANBL: J10.1 UT13.100(CANL)
CASE-LED1: RT107.1 RT108.1 UT13.76(EPWM6A)
CASE-LED2: UT13.75(EPWM6B)
CASE-TEMP: CB8.1 RT27.2 UT13.63(A15)
CHS-PWM: RT118.1 UT13.36(EPWM3A)
CHS-PWM-N: J3.4 UT25.3(Z1)
CHS-PWM-P: J3.3 UT25.2(Y1)
CLS-PWM: RT113.1 UT13.35(EPWM3B)
CLS-PWM-N: J3.6 UT25.5(Z2)
CLS-PWM-P: J3.5 UT25.6(Y2)
EXT-Current: CB12.1 RT23.2 UT13.70(AA1)
Global-FAULT: UB3.4(Y) UT13.73(P15)
IA-m: J4.2 RT62.1 RT72.1
IB-m: J5.2 RT64.1 RT73.1
IC-m: J6.2 RT66.1 RT74.1
IEXT-m: J10.6 RT36.1 RT38.1
LED-G: RT13.1 UT13.49(P41)
LED-R: RT11.1 UT13.47(P65)
LED-Y: RT12.1 UT13.48(P52)
QEA_A: J10.14 UT13.89(QEA_A)
QEA_B: J10.16 UT13.90(QEA_B)
QEA_I: J10.18 UT13.91(QEA_I)
QEB_A: J10.22 UT13.94(QEB_A)
QEB_B: J10.24 UT13.95(QEB_B)
QEB_I: J10.26 UT13.96(QEB_I)
Shutdown+15V: RT124.1 RT127.1 UT13.13(P124)
Shutdown-15V: RT115.1 RT117.1 UT13.12(P125)
VA-M: J7.2(PIN2) RB21.1
VA-P: J7.1(PIN1) RT99.1
VB-M: J7.4(PIN4) RB13.1
VB-P: J7.3(PIN3) RT81.1
VC-M: J7.6(PIN6) RB7.1
VC-P: J7.5(PIN5) RT35.1
VDC-M: J8.2 RB1.1
VDC-P: J8.1 RT10.1
Vsense-A: CB4.1 RT18.2 UT13.27(AC2)
Vsense-B: CB3.1 RT19.2 UT13.26(AA3)
Vsense-C: CB2.1 RT20.2 UT13.25(AB3)
Vsense-DC: CB1.1 RT21.2 UT13.24(AC3)
N07282: RT100.2 UT19.4(G)
N07299: RT101.1 UT19.12(~{G})
N07508: RT106.2 UT20.4(G)
N07516: RT89.1 UT20.12(~{G})
N07693: RT112.2 UT24.4(EN)
N07878: RT120.2 UT25.4(EN)
N09835: CB21.1 RB28.2 UT24.1(A1)
N10049: CB23.1 RB29.2 UT24.7(A2)
N10085: CB22.1 RB30.2 UT24.9(A3)
N10121: CB20.1 RB27.2 UT24.15(A4)
N11382: RT114.2 UT24.12(~{EN})
N11987: RT111.2 UT25.12(~{EN})
N12714: CT67.1 RT118.2 UT25.1(A1)
N12754: CT64.1 RT113.2 UT25.7(A2)
N16187: CT23.2 RT24.1 UT3.1(OUT) UT3.4(IN-)
N16636: CT23.1 RT41.2 RT42.1
N16643: CT15.2 RT42.2 UT3.3(IN+)
N18013: CT24.1 RT43.2 RT44.1
N18021: CT24.2 RT25.1 UT4.1(OUT) UT4.4(IN-)
N18093: CT16.2 RT44.2 UT4.3(IN+)
N18488: CT25.1 RT45.2 RT46.1
N18496: CT25.2 RT26.1 UT5.1(OUT) UT5.4(IN-)
N18568: CT17.2 RT46.2 UT5.3(IN+)
N28683: CT27.2 RT15.1 RT59.2 UT7.1(OUT)
N28695: CT27.1 RT59.1 UT7.4(IN-)
N28775: CT20.1 RT52.2 UT7.3(IN+)
N28956: CT31.1 RT51.2 RT52.1 RT62.2 RT63.2
N31299: CT32.1 RT53.2 RT54.1 RT64.2 RT65.2
N31469: CT21.1 RT54.2 UT8.3(IN+)
N31505: CT28.2 RT16.1 RT60.2 UT8.1(OUT)
N31529: CT28.1 RT60.1 UT8.4(IN-)
N32358: CT33.1 RT55.2 RT56.1 RT66.2 RT67.2
N32528: CT22.1 RT56.2 UT9.3(IN+)
N32564: CT29.2 RT17.1 RT61.2 UT9.1(OUT)
N32588: CT29.1 RT61.1 UT9.4(IN-)
N35636: RB23.2 RB24.1
N35646: RB24.2 RB25.1
N35650: RB25.2 RB26.1
N35794: RT96.1 RT97.2
N35798: RT95.1 RT96.2
N35802: RT94.1 RT95.2
N35806: CT54.2 RT90.1 RT93.2 RT94.2
N45499: RT78.1 RT79.2
N45503: RT77.1 RT78.2
N45507: RT76.1 RT77.2
N45511: CT38.2 RT68.1 RT75.2 RT76.2
N45813: RB15.2 RB16.1
N45817: RB16.2 RB17.1
N45821: RB17.2 RB18.1
N45825: CT36.1 RB18.2 RT40.1 RT58.1
N47166: RT32.1 RT33.2
N47170: RT31.1 RT32.2
N47174: RT30.1 RT31.2
N47178: CT6.2 RT28.1 RT29.2 RT30.2
N47480: RB9.2 RB10.1
N47484: RB10.2 RB11.1
N47488: RB11.2 RB12.1
N47492: CT5.1 RB12.2 RT14.1 RT22.1
N51028: RT98.1 RT99.2
N51064: RB21.2 RB22.1
N51070: RT97.1 RT98.2
N51074: RB22.2 RB23.1
N51202: RT80.1 RT81.2
N51206: RT79.1 RT80.2
N51246: RB13.2 RB14.1
N51250: RB14.2 RB15.1
N51378: RT34.1 RT35.2
N51382: RT33.1 RT34.2
N51422: RB7.2 RB8.1
N51426: RB8.2 RB9.1
N62914: CT14.1 RT37.2 RT38.2 RT39.1 RT49.2
N63160: CT19.1 RT39.2 UT10.3(IN+)
N63220: CT34.2 RT23.1 RT57.2 UT10.1(OUT)
N63260: CT34.1 RT57.1 UT10.4(IN-)
N66752: CT51.2 RT18.1 RT88.2 UT18.1(OUT)
N66907: CT51.1 RB26.2 RT87.1 RT88.1
N66989: RT87.2 UT18.4(IN-)
N67029: RT90.2 UT18.3(IN+)
N74358: RT68.2 UT12.3(IN+)
N74448: CT36.2 RT19.1 RT58.2 UT12.1(OUT)
N74460: RT40.2 UT12.4(IN-)
N75234: RT28.2 UT2.3(IN+)
N75324: CT5.2 RT20.1 RT22.2 UT2.1(OUT)
N75336: RT14.2 UT2.4(IN-)
N76078: CT3.2 RT3.1 RT4.2 RT5.2
N76134: RT3.2 UT1.3(IN+)
N76224: CT2.2 RT2.2 RT21.1 UT1.1(OUT)
N76236: RT1.2 UT1.4(IN-)
N76260: CT2.1 RB6.2 RT1.1 RT2.1
N78650: CT26.1 RT47.2 RT48.1
N78658: CT26.2 RT27.1 UT6.1(OUT) UT6.4(IN-)
N78724: CT18.2 RT48.2 UT6.3(IN+)
N79088: CT43.2 RT47.1 RT82.2 RT83.1
N88263: DT5.1(A) RT110.2
N88433: DT4.1(A) RT109.2
N88603: DT12.1(A) RT138.2
N88777: DT11.1(A) RT137.2
N93191: DT1.1(A) RT11.2
N93195: DT3.1(A) RT13.2
N93199: DT2.1(A) RT12.2
N95779: RT123.1 RT128.1 UT28.3(D) UT29.13(~SHDN)
N96795: RT131.1 RT132.1 UT30.3(D) UT31.13(~SHDN)
N97055: CT84.1 DT9.1(C) QT1.1(S) RT129.2 RT135.1
N97211: CT79.2 RT130.1 UT31.2(Vc)
N97283: CT75.1 RT130.2
N139937: RT9.1 RT10.2
N139941: RT8.1 RT9.2
N139945: RT7.1 RT8.2
N139949: RT6.1 RT7.2
N139953: RT5.1 RT6.2
N140053: RB1.2 RB2.1
N140057: RB2.2 RB3.1
N140061: RB3.2 RB4.1
N140065: RB4.2 RB5.1
N140069: RB5.2 RB6.1
N141814: CB17.1 RB19.2
N143941: CB18.1 RB20.2
N145779: CT69.1 RT115.2 UT28.1(G)
N146352: CT77.1 RT127.2 UT30.1(G)
N147166: QT2.1(S) QT3.1(S)
N148075: QT2.4(G) QT3.4(G) RT139.2 UT32.10(GATE)
N148197: CT87.1 RT139.1
N148540: QT3.5(D) RT141.1 UT32.9(SENSE)
N149103: RT143.1 RT144.2 UT32.6(/SHDN)
N149107: RT142.1 RT143.2 UT32.2(UV)
N149113: RT140.1 RT142.2 UT32.3(OV)
N149983: CT88.1 UT32.4(RETRY)
N150621: RT136.2 UT32.7(/FAULT)
N177905: DT7.1(ANODE) RT119.2
N177925: DT6.2(CATHODE) DT7.2(CATHODE) UT21.3(D)
N178332: DT6.1(ANODE) RT116.2
N179044: CT59.1 RT108.2 UT21.1(G)
N200782: RT134.2 UT31.14(RT)
N203219: RT133.2 UT31.4(~FAULT)
N204184: DT9.2(A) LT14.2 UT31.6(SW1) UT31.9(SW2)
N204300: RT129.1 UT31.1(FB)
N204715: CT80.2 UT31.15(SS)
N205443: DT10.C(CATHODE) QT1.4(G) RT135.2 UT31.3(GATE)
N208883: CT82.1 LT13.3 UT29.6(SW1) UT29.9(SW2)
N209249: RT121.1 UT29.1(FB)
N209309: RT125.2 UT29.4(~FAULT)
N209373: RT126.2 UT29.14(RT)
N209381: CT73.2 RT122.1 UT29.2(Vc)
N209421: CT74.2 UT29.15(SS)
N209493: CT71.1 RT122.2
N213371: CT82.2 DT8.2(A) LT13.4
N273504: RT41.1 RT84.2 UT14.5(Q)
N273798: CT40.2 UT14.6(CEXT)
N273802: CT40.1 RT69.2 UT14.7(REXT/CEXT)
N275299: RT43.1 RT85.2 UT15.5(Q)
N275399: CT41.1 RT70.2 UT15.7(REXT/CEXT)
N275407: CT41.2 UT15.6(CEXT)
N275841: RT45.1 RT86.2 UT16.5(Q)
N275941: CT42.1 RT71.2 UT16.7(REXT/CEXT)
N275949: CT42.2 UT16.6(CEXT)

Not connected (* = marked no-connect by the designer): J9 1(NC1) 4(NC2) 6(O(V-)) 8(NC3); QT1 2(S1) 3(S2) 6(D1) 7(D2) 8(D3); QT2 2(S1) 3(S2) 6(D1) 7(D2) 8(D3); QT3 2(S1) 3(S2) 6(D1) 7(D2) 8(D3); UT13 2(P32) 5(P67) 6(P111) 7(P60) 8(P22) 9(P105) 10(P104) 11(P29) 14(P59) 15(P58) 16(RST_1) 17(P122) 18(P123) 19(P61) 23(A14) 31(DAC2) 32(DAC1) 33(P16) 34(P24) 43(P139) 44(P56) 50(P40) 56(RST_2) 64(AC5)* 65(AB5)* 68(AB4)* 71(DAC4) 72(DAC3) 77(EPWM5B) 81(AD0) 83(AD1) 85(AD2) 87(AD3); UT17 8(NC); UT20 9(B3) 10(A3) 11(Y3) 13(Y4) 14(A4) 15(B4); UT22 17(Y2) 18(Y1); UT23 11(Y8) 12(Y7) 13(Y6) 14(Y5) 15(Y4); UT25 9(A3) 10(Y3) 11(Z3) 13(Z4) 14(Y4) 15(A4); UT29 3(GATE) 7(SW11) 8(SW12) 10(SW21) 11(SW22) 12(CLKOUT); UT31 7(SW11) 8(SW12) 10(SW21) 11(SW22) 12(CLKOUT)

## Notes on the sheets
sheet 1
- Revision History:
- V1.0 1/21/2019
  Initial design release
  For internal use not for resale
  Using LAUNCHXL-F28379D
- V1.1 5/15/2019
  Added direct connection to RTD/NTC module signals for eCAP of FM type
  Added one-shot circuit for analog measurement of FM type RTD signal
  Renumbered connectors in order
  Added HV Warning to silkscreen
  Added additional mounting holes next to GD connectors to prevent flex when removing ribbon cable
  Increased DC bus connector hole size
  Changed silkscreen from ABC to UVW
  Moved case LEDs to under logo in lid
- V1.2 9/4/2019
  Corrected 74LV123 pinout
  Change LT3581 soft start capacitor to 0.1uF
  Renumber Ref Des
  Change current sense resistor footprint from 1210 to 1206
sheet 2
- DC INPUT
- MSD7342-682MLC
- Power Supply PSAC60M-120
  993-1107-ND
- Plug: CP3-1000-ND
- Place close to
  external connector
- Place close to
  external connector
- Fan Power
- 2V @5mA
  0805 Green
sheet 3
- HV Differential
- HV DC BUS
- 300V max, 2/5 W, 0.1%
- VEXT Fc = 6.5 kHz
- VDC Fc = 6.5 kHz
sheet 4
- 209MER-ND
  909GME-ND
  182-109FE-ND
  NOR1354-ND
sheet 5
- fc = 1002 Hz
  Q = 0.7048
sheet 6
- Rm,max = Ns * (Ucmin - 0.5V)/ Ip - Rs,max -1.1
  Ns = 5000
  Rs,max = 52.8
  Ucmin = 14.25
- Rm,max = 5000 * (14.25 - 0.5V)/ 800 - 52.8 -1.1 = 32ohms
  Is,max = +/- 160mA
  Prm,max = .16^2*30 = 0.768 W
- F28379D ADC sampling Cap = 14.5pF
sheet 7
- NON-ISOLATED
- F28379D ADC sampling Cap = 14.5pF
- Launchpad connector TLW-110-05-T-D, PPTC031LFBN-RC, and PPTC051LFBN-RC
- Aux. Connector
- NON-ISOLATED
- 3M1769-ND
  3M1741-ND
  3M1747-ND
  MPB26A-ND
- AB4,AB5,AC5 not present on LQFP
- 0805 Red Diff
- 0805 Yellow Clear
  1.8V @ 5mA
- 0805 Green Diff
- Purple
  2.8V @ 5mA
sheet 8
- 296-18698-1-ND
